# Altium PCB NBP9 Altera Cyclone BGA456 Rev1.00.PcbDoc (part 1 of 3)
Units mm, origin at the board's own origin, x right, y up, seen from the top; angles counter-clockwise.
Board outline 69 x 80.99 mm, 6 copper layers (Top Layer, MidLayer1, InternalPlane1, InternalPlane2, MidLayer2, Bottom Layer); 105 components, 269 nets, 899 pads, 453 vias.
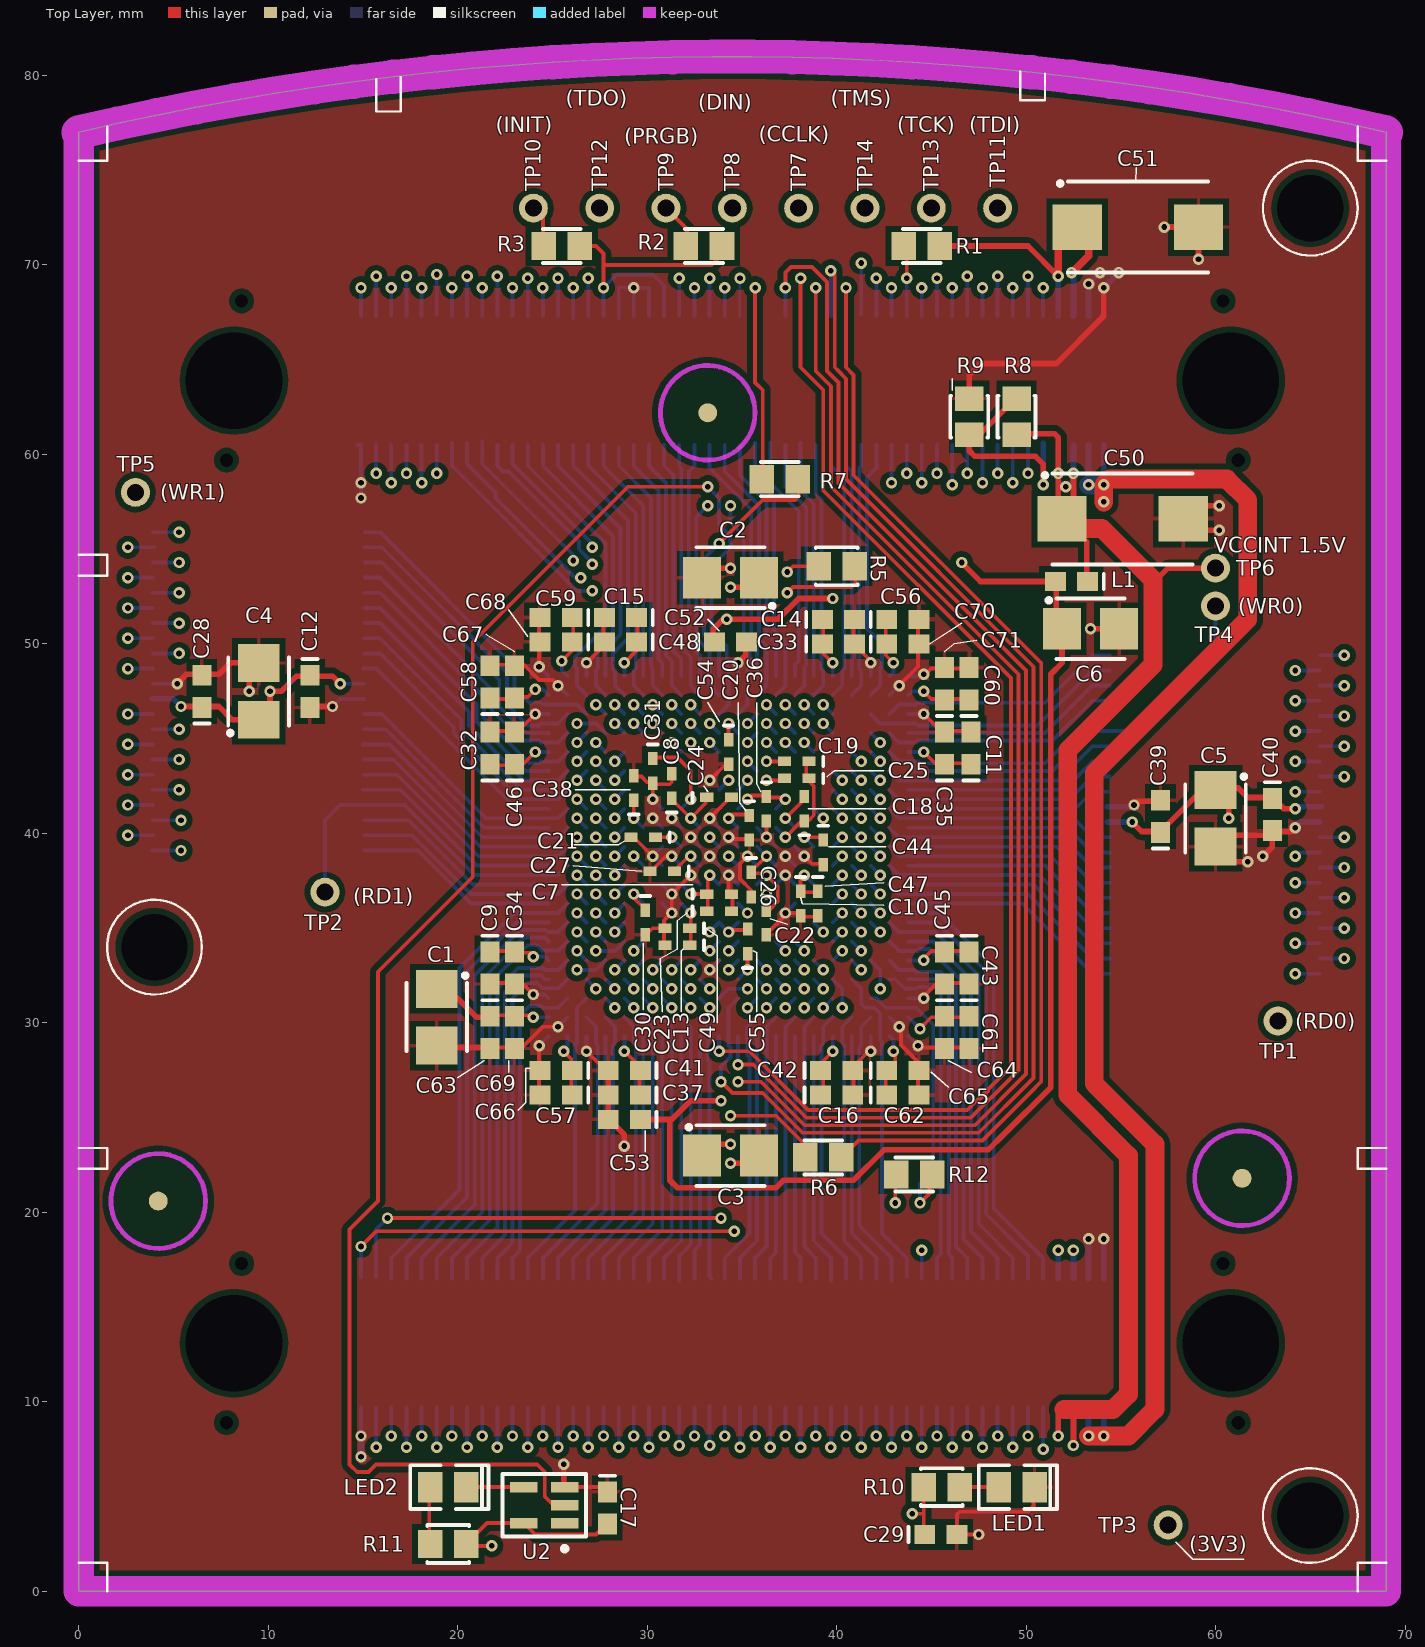
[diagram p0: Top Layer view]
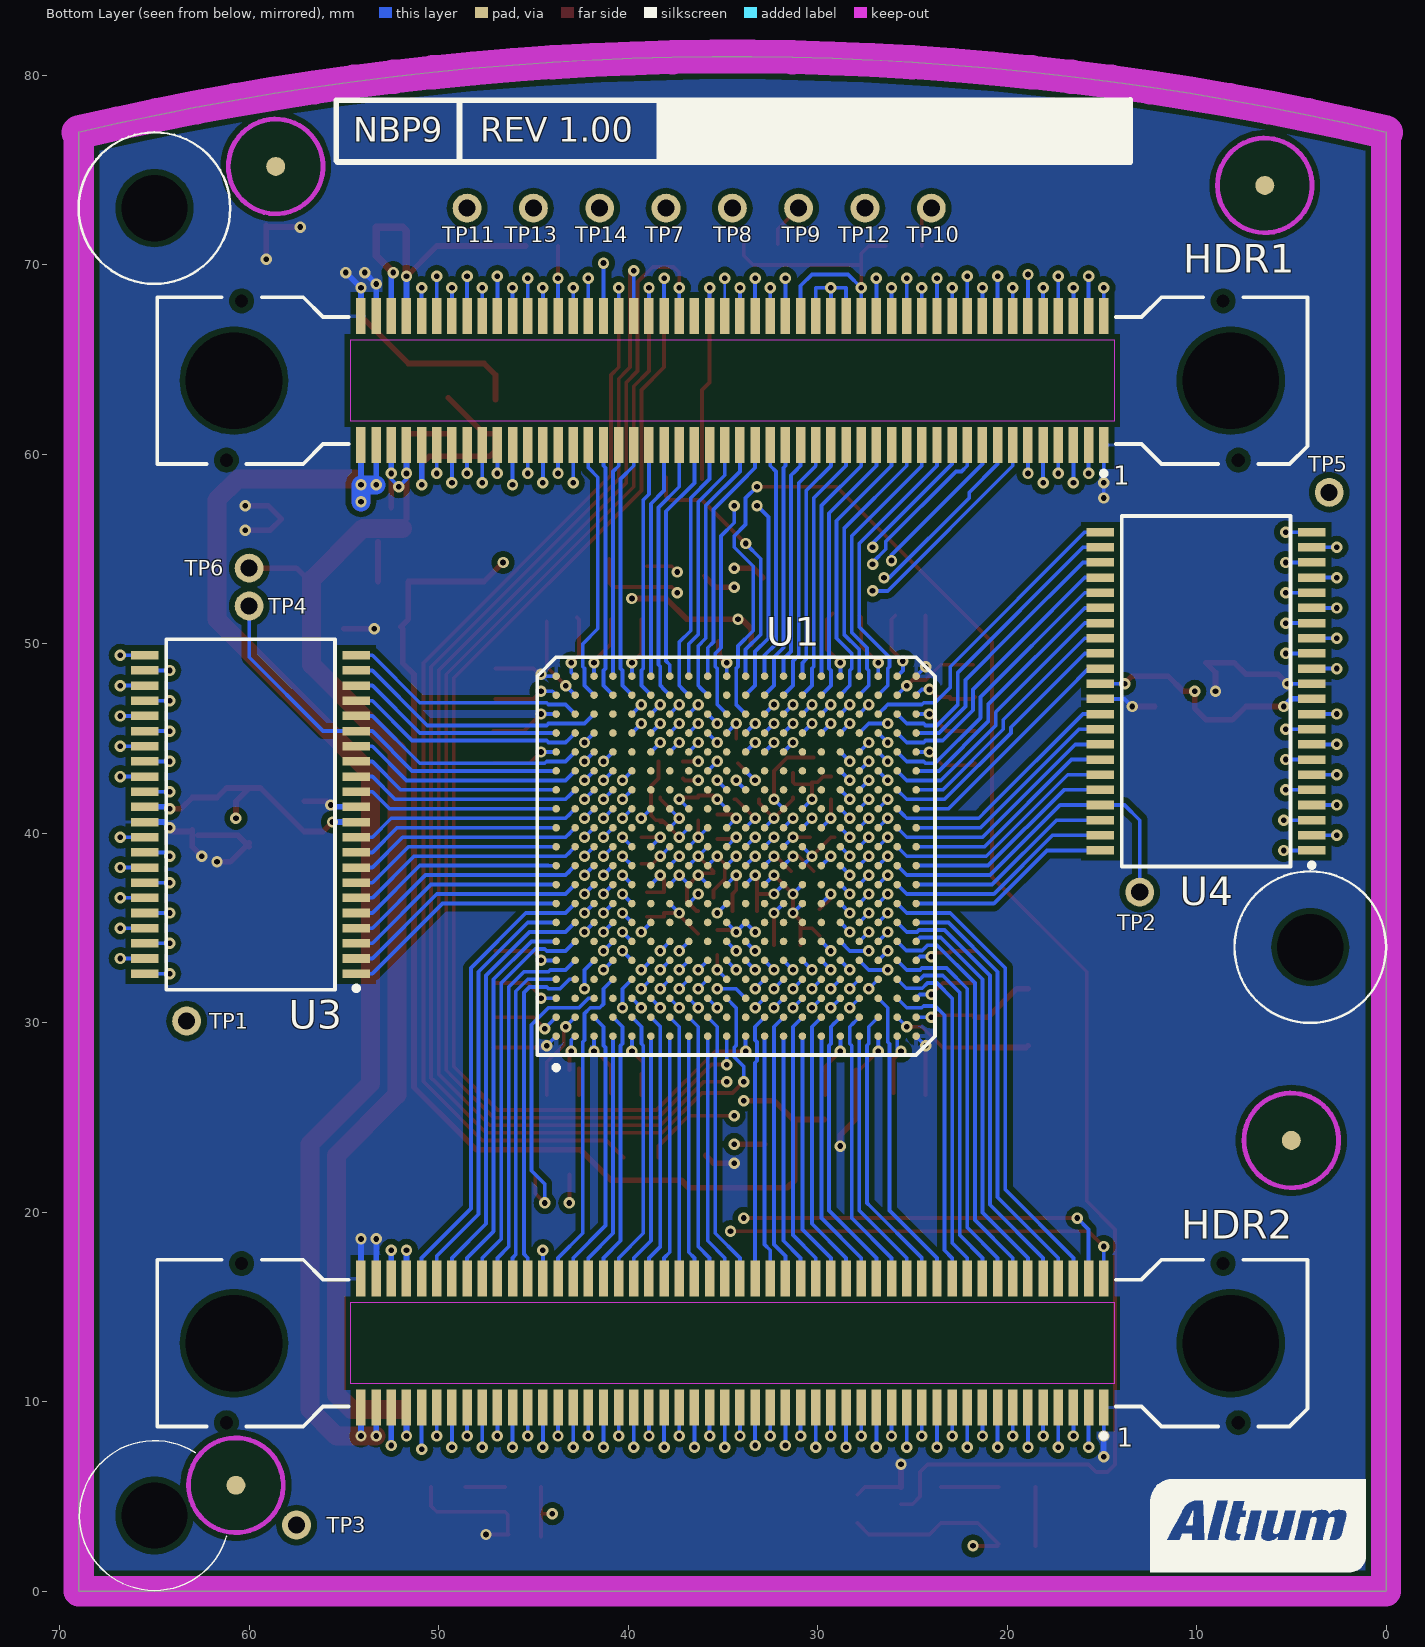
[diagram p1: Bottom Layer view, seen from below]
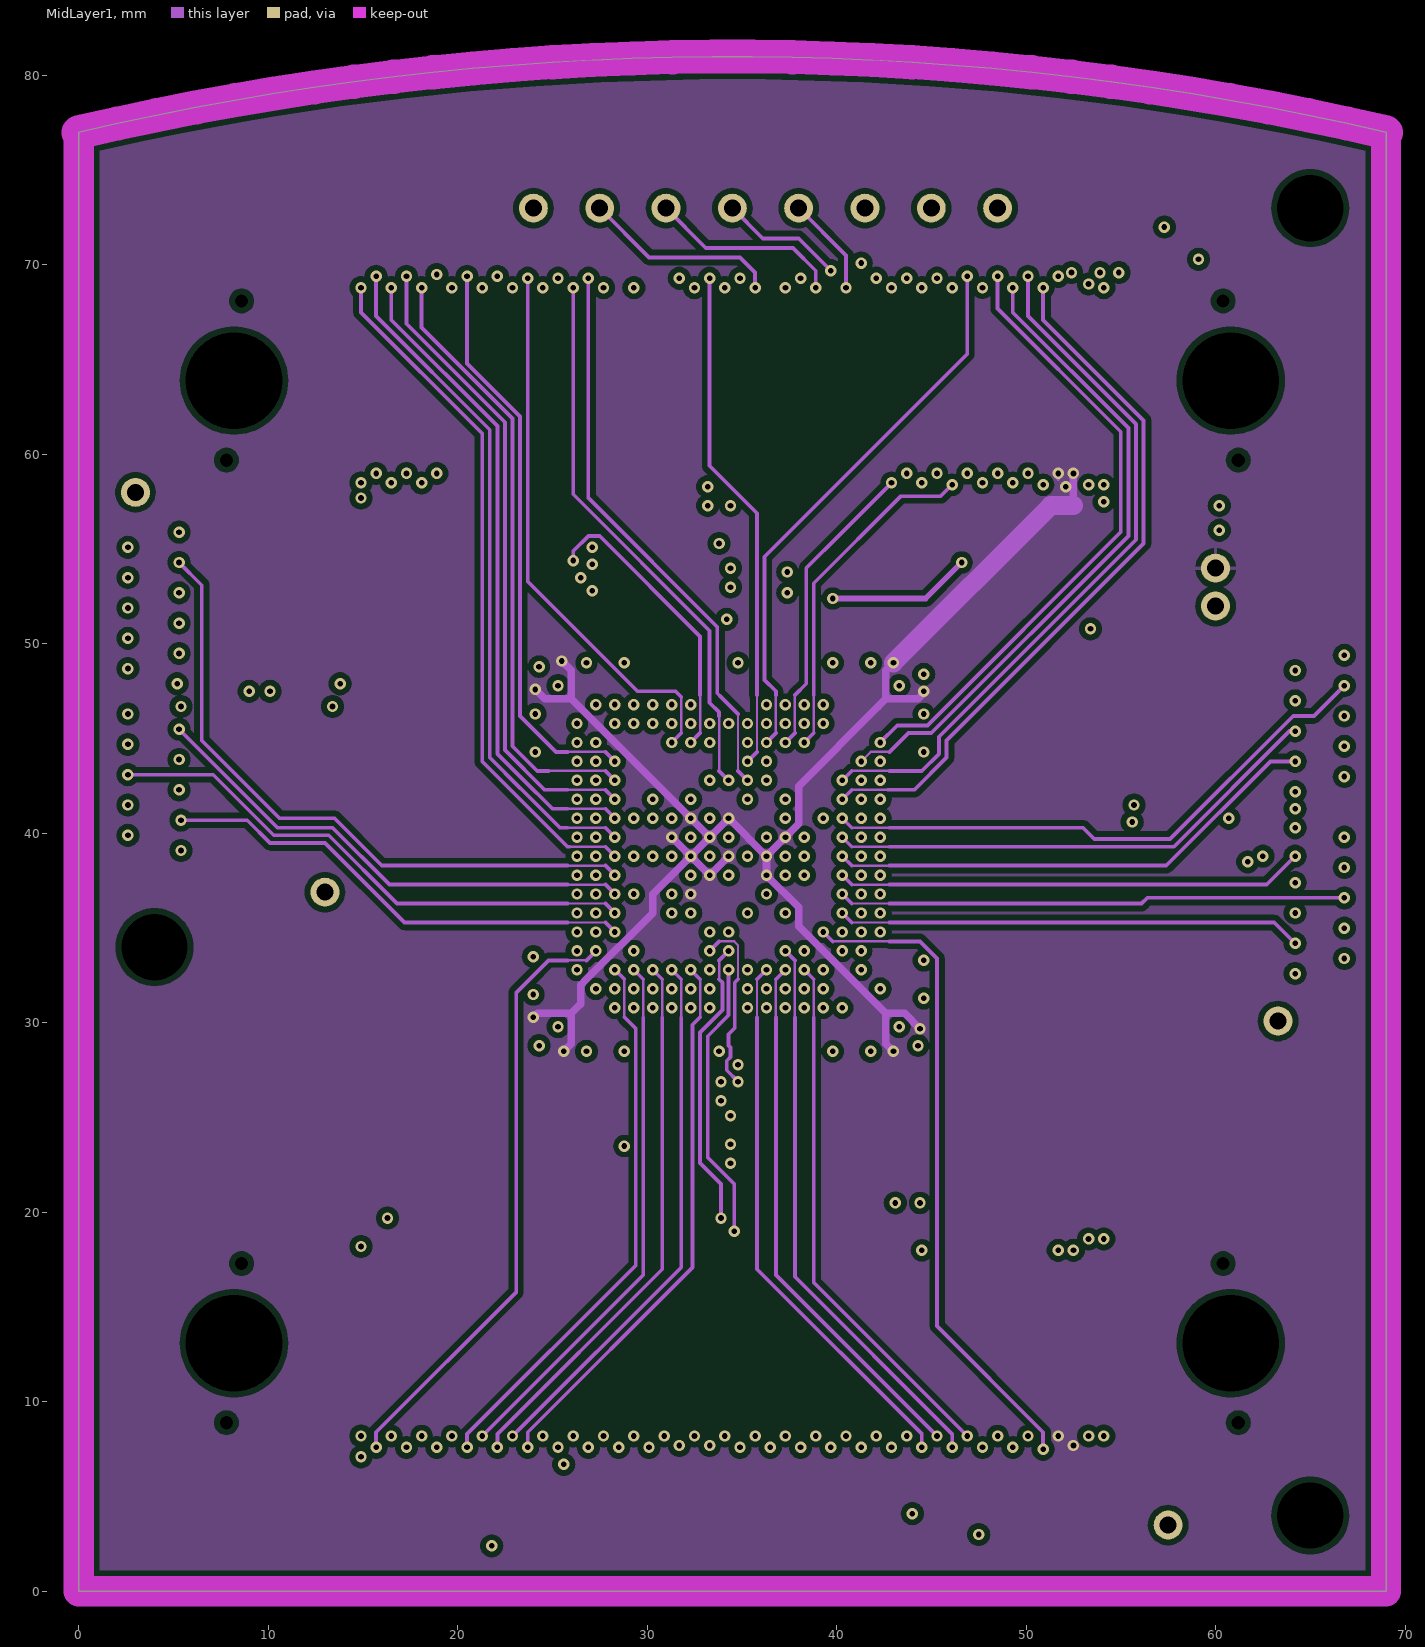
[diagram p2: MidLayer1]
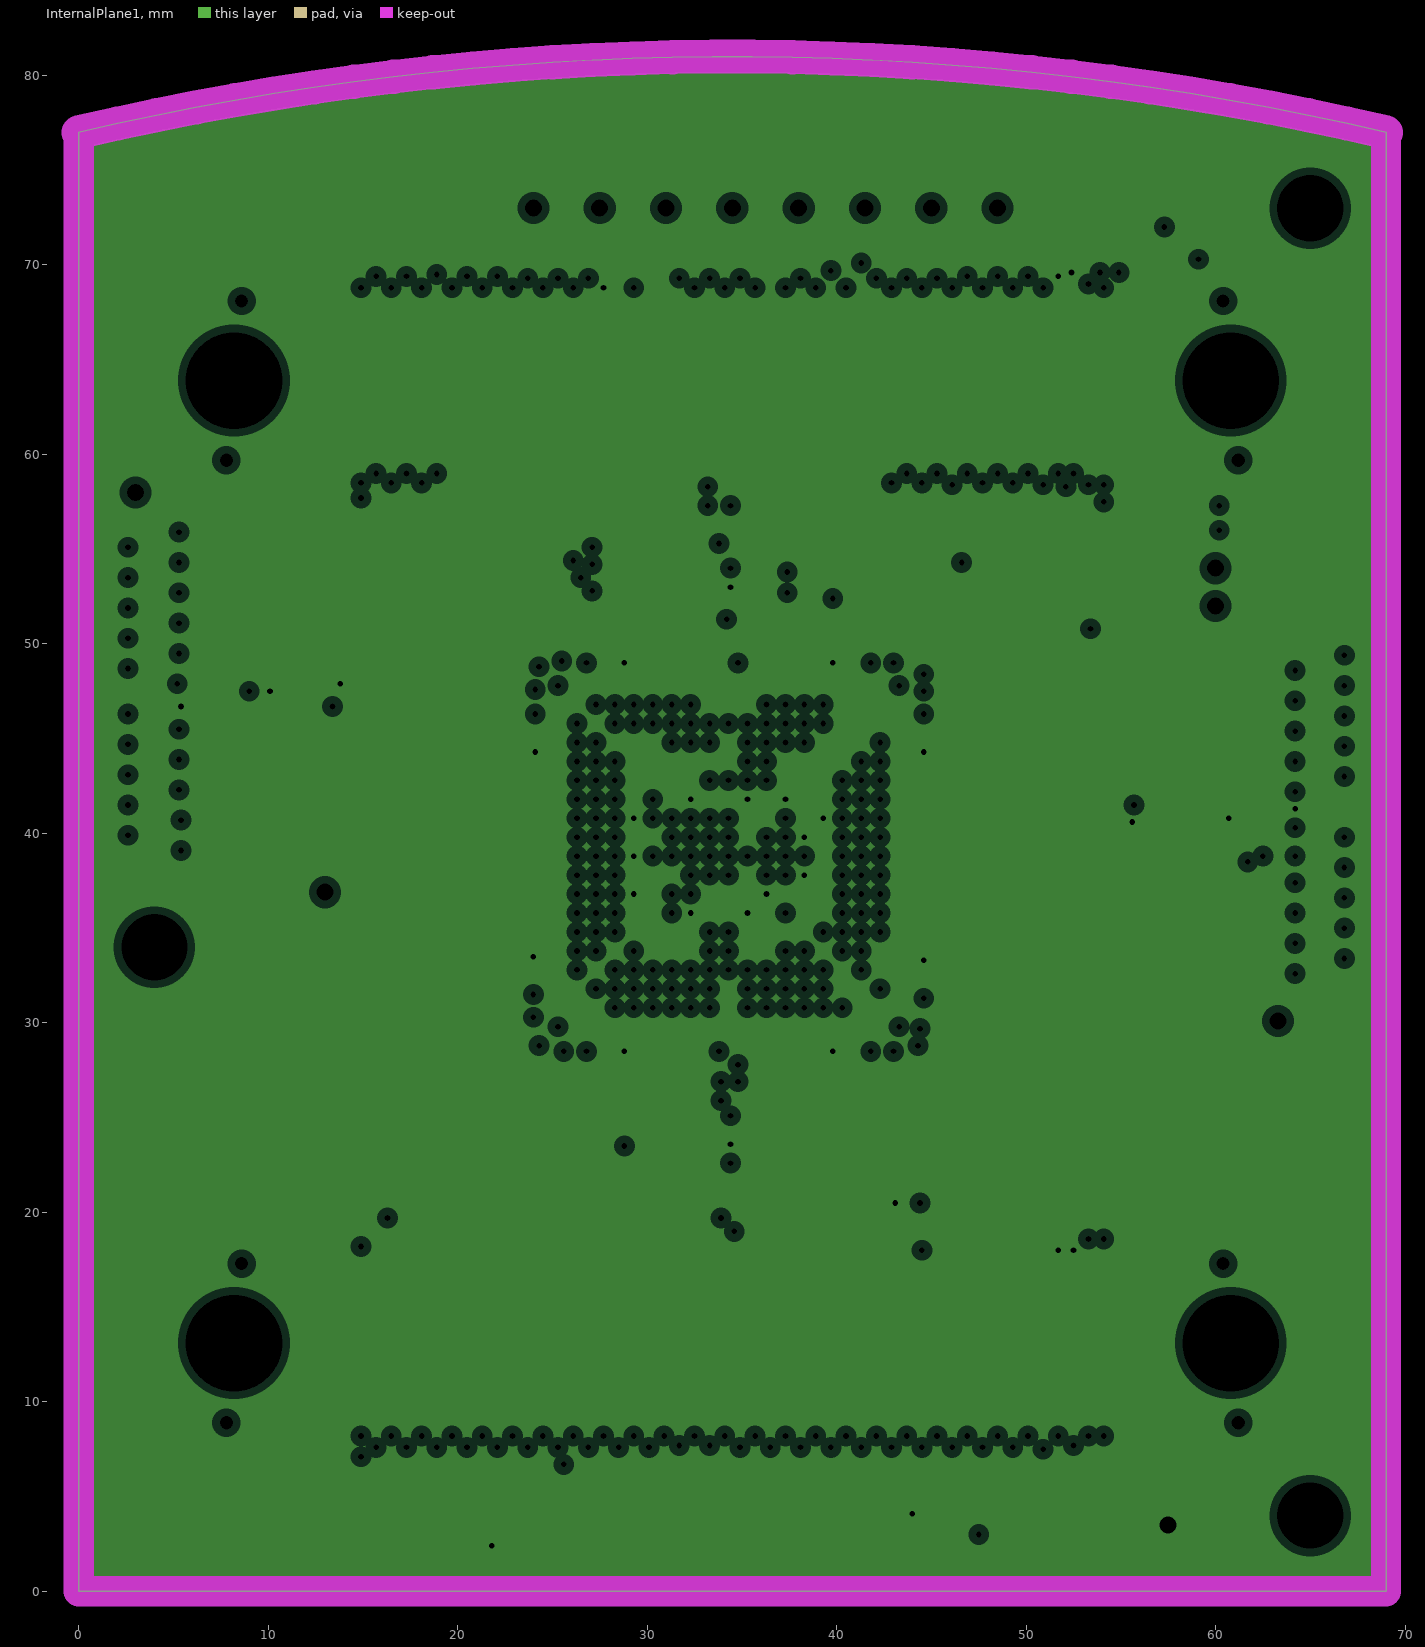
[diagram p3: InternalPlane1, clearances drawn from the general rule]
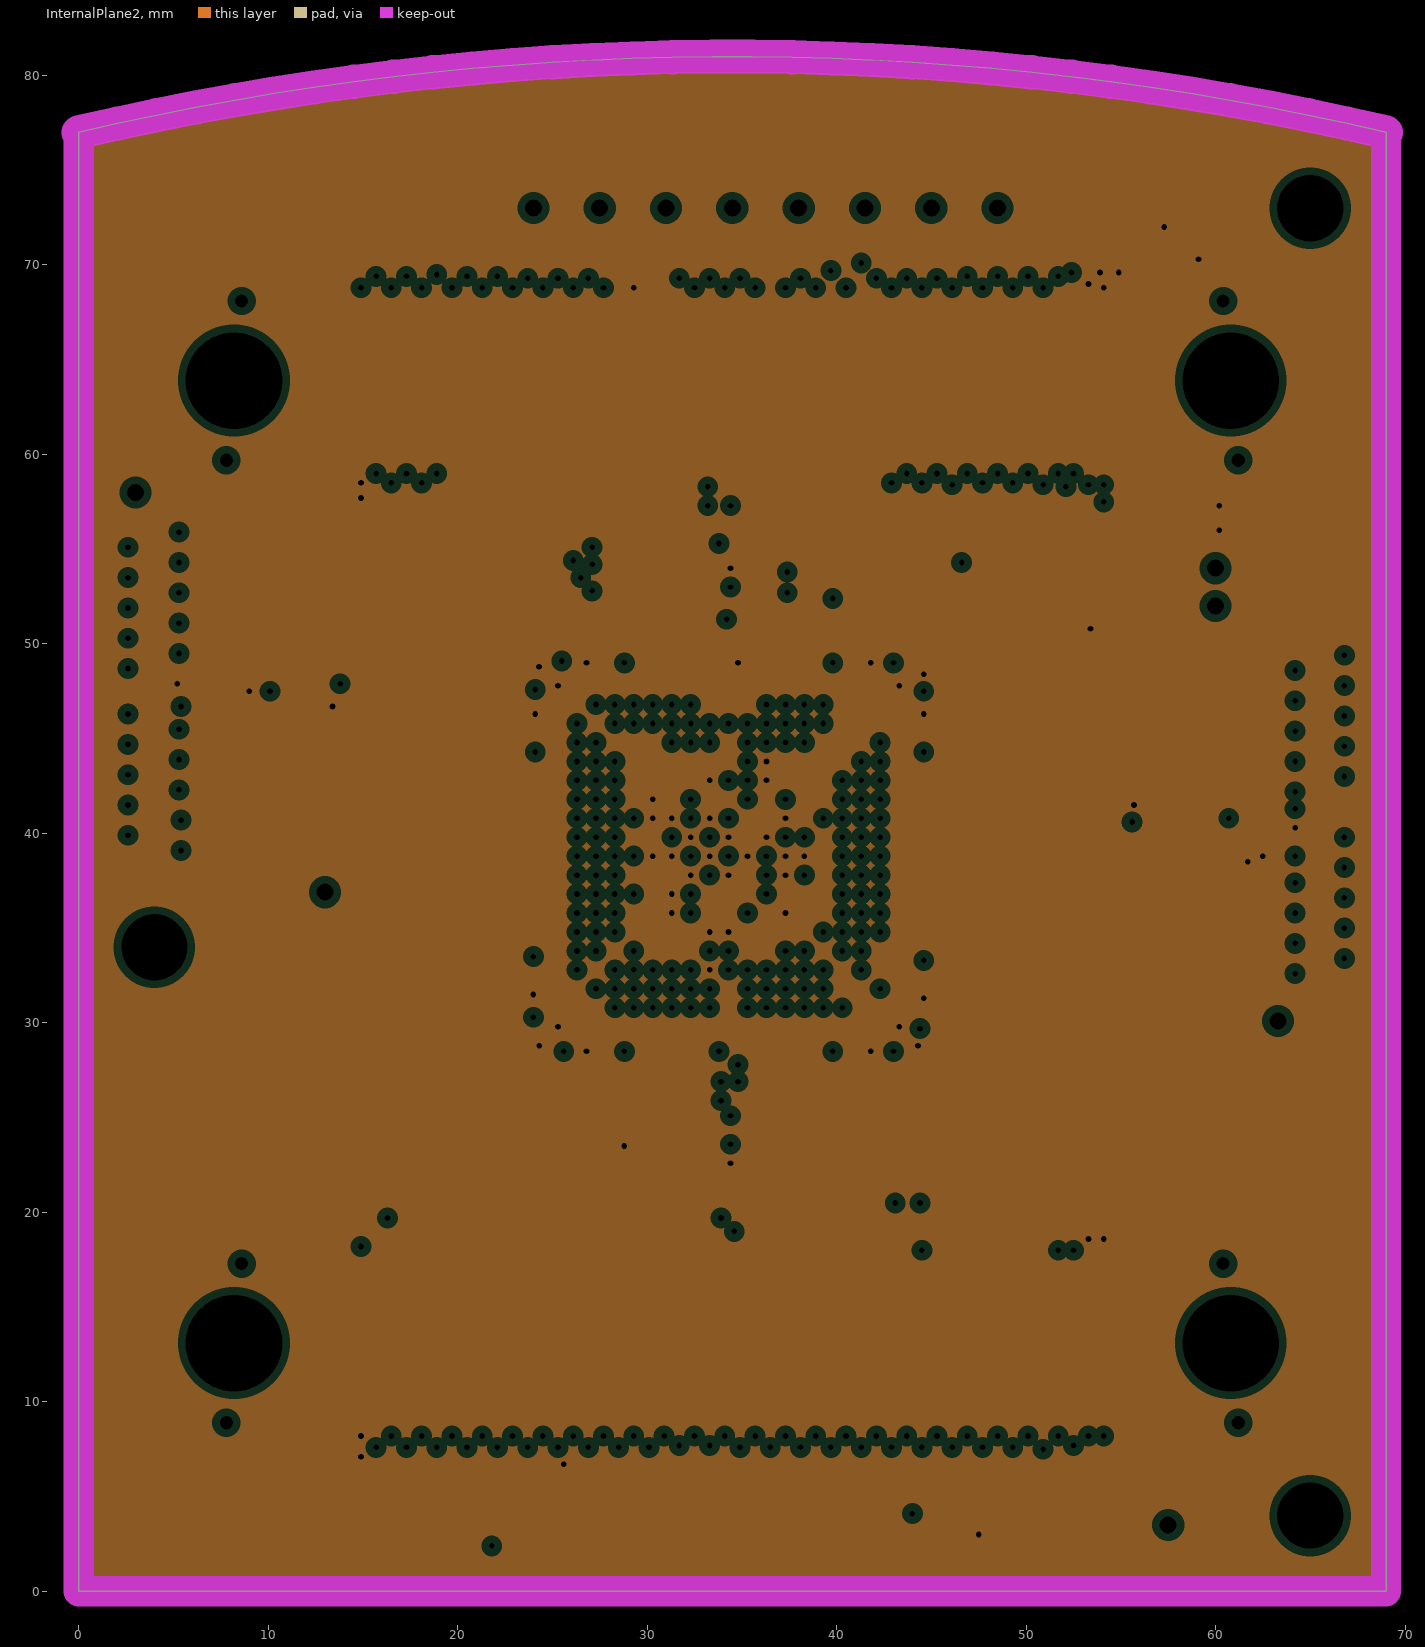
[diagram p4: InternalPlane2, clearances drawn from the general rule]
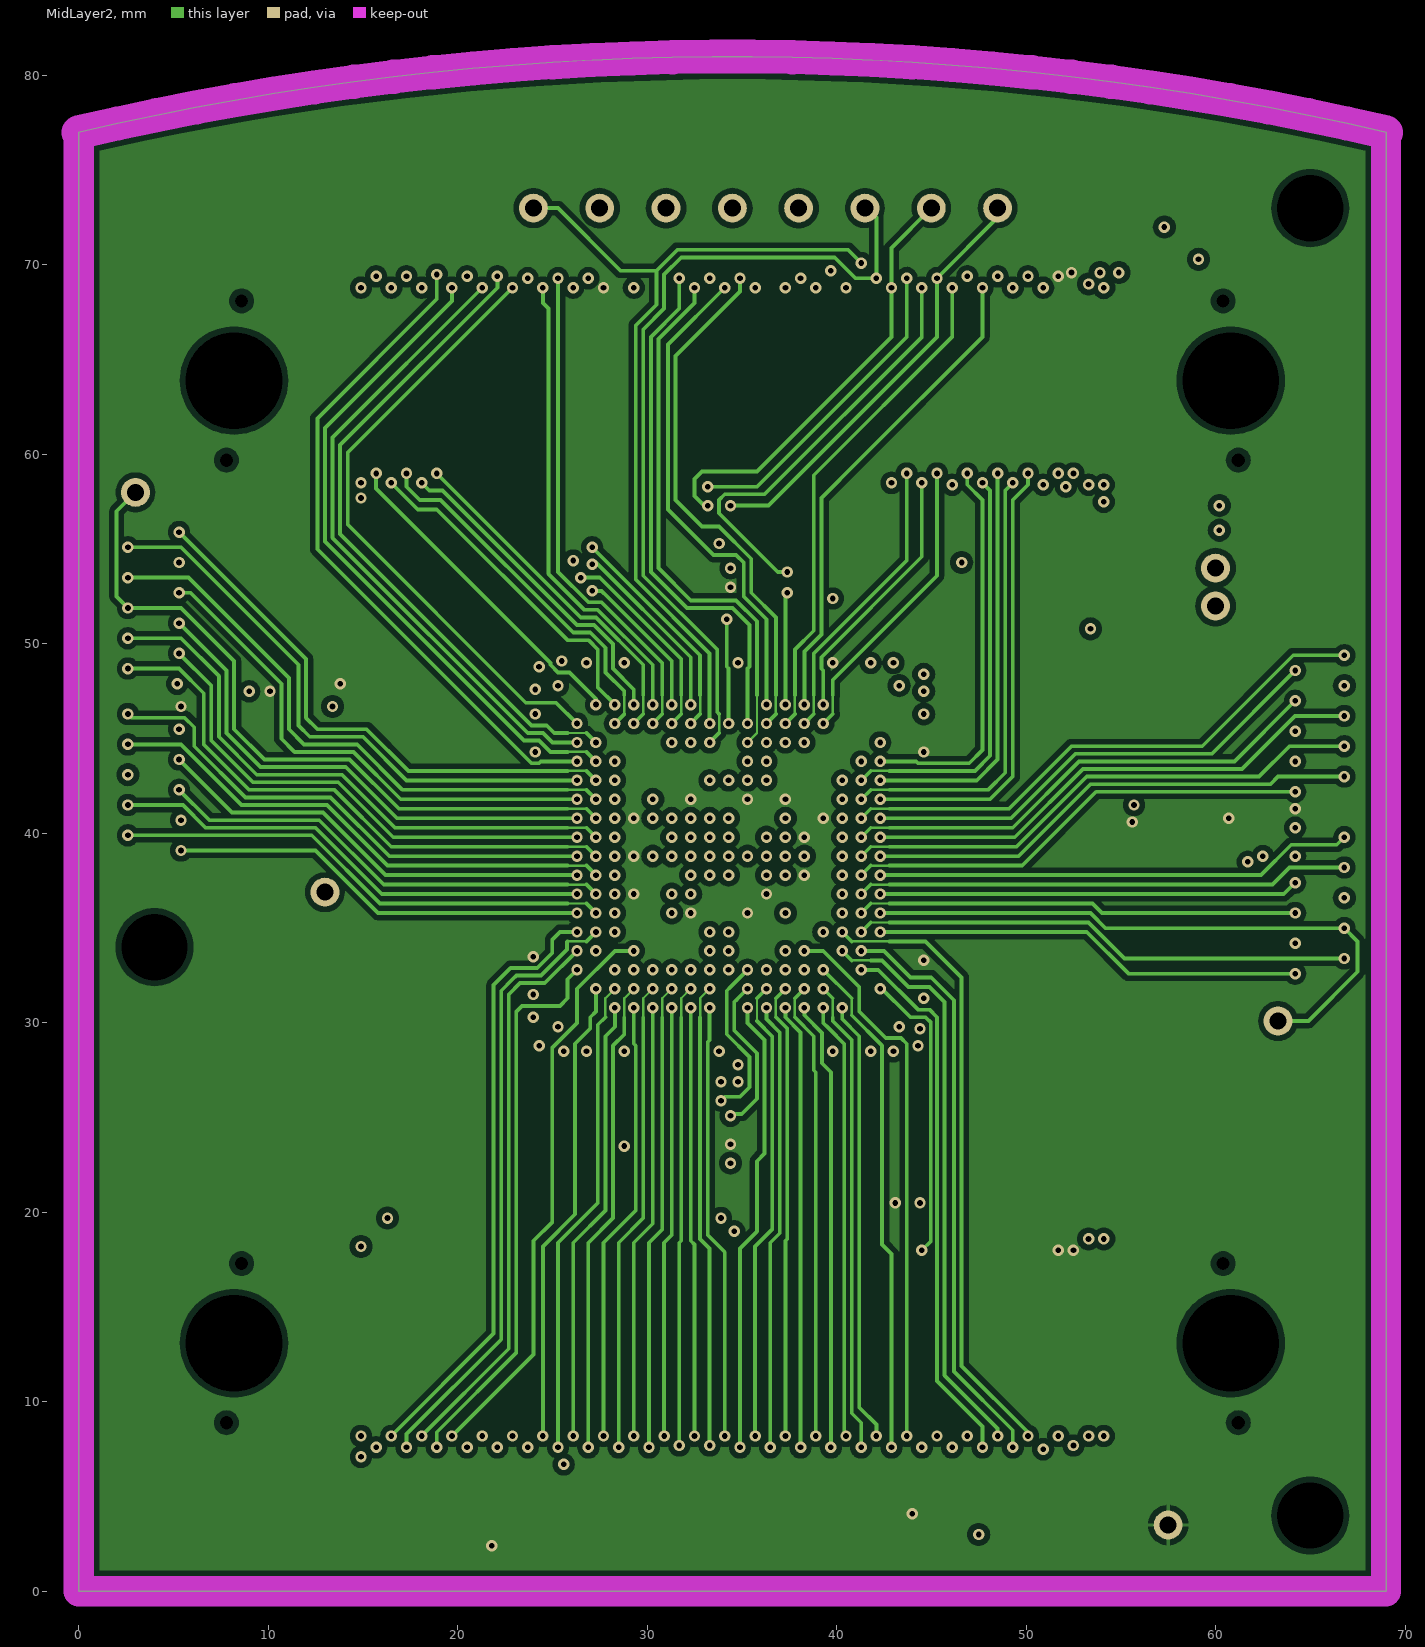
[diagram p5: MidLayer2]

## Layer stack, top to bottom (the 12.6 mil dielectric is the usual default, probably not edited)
Top Layer: signal copper 0.0356
Dielectric: core 0.32, FR-4, Dk 4.8
MidLayer1: signal copper 0.0356
Dielectric: prepreg 0.32, FR-4, Dk 4.8
InternalPlane1: plane copper 0.0356, net VCC
Dielectric: core 0.32, FR-4, Dk 4.8
InternalPlane2: plane copper 0.0356, net GND
Dielectric: prepreg 0.32, FR-4, Dk 4.8
MidLayer2: signal copper 0.0356
Dielectric: core 0.32, FR-4, Dk 4.8
Bottom Layer: signal copper 0.0356

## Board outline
0,0 0.001,77 cw(c34.5,-69.801) 69,77 69,0

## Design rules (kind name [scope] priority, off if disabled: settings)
Clearance Clearance_Polygons [InPolygon] p1: gap=0.3
Clearance "InnerLayer Track-Via Clearance" [OnMid And IsTrack vs IsVia] p2: gap=0.127
Clearance "Via-Via Clearance" [IsVia vs IsVia] p3: gap=0.3
Clearance "Pad-Pad Clearance Same Net" [IsPad vs IsPad] p4: gap=0.254
Clearance "Via-Pad Clearance" [IsVia vs IsPad] p5: gap=0.2
Clearance "General Clearance" [All] p6: gap=0.125
ComponentClearance [All] p1: gap=0.2 collisioncheckmode=3 verticalgap=0.254 showdistances=FALSE
FabricationTestPointUsage TestPointUsage [All] p1 off: valid=0 allowmultiple=FALSE
FabricationTestpoint Testpoint [All] p1 off: side=3 testpointundercomponent=TRUE minsize=1.016 maxsize=2.54 preferedsize=1.524 minholesize=0 maxholesize=1.016 preferedholesize=0.813 testpointgrid=0.025 allowsidetop=TRUE allowsidebottom=TRUE usegrid=TRUE gridtolerance=0
HoleSize [All] p1: absolutevalues=TRUE maxlimit=5.2 minlimit=0.25 maxpercent=80.000 minpercent=20.000
PlaneClearance [All] p1: clearance=0.4
PlaneConnect [All] p1: planeconnectstyle=Direct reliefexpansion=0.5 reliefentries=4 reliefconductorwidth=0.25 reliefairgap=0.25
PolygonConnect [All] p1: connectstyle=Relief reliefconductorwidth=0.2 reliefentries=4 polygonreliefangle="90 Angle"
RoutingVias [All] p1: holewidth=0.3 width=0.6 viastyle="Through Hole" minholewidth=0.3 minwidth=0.6 maxholewidth=0.5 maxwidth=0.9
SMDNeckDown [All] p1: percent=100.000
SilkscreenOverComponentPads [All] p1: minsilkscreentomaskgap=0.254
SolderMaskExpansion SolderMaskExpansion_Vias [IsVia] p1: expansion=-0.65
SolderMaskExpansion [All] p2: expansion=0.1
Width [All] p1: maxlimit=2.5 minlimit=0.127 preferedwidth=0.4 toplayer_minwidth=0.2 toplayer_prefwidth=0.2 midlayer2_prefwidth=0.2 bottomlayer_prefwidth=0.3 minimp=50.000000 maximp=50.000000 favimp=50.000000
21 further rules are at their usual default settings.

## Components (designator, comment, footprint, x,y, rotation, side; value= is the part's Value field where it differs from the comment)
C1 "10uF" MCCT-B 18.9,30.3 r270 top
C2 "10uF" MCCT-B 34.4,53.5 r180 top
C3 "10uF" MCCT-B 34.4,23 r0 top
C4 "10uF" MCCT-B 9.5,47.5 r90 top
C5 "10uF" MCCT-B 60,40.8 r270 top
C6 "10uF" MCCT-B 53.4,50.8 r0 top
C7 "220nF" CC1005-0402 33.8,36.8 r0 top
C8 "220nF" CC1005-0402 31.3,42.5 r90 top
C9 "220nF" CC1608-0603 21.7,32.9 r270 top
C10 "220nF" CC1005-0402 38.1,36.3 r270 top
C11 "220nF" CC1608-0603 47.1,44.5 r90 top
C12 "220nF" CC1608-0603 12.2,47.5 r270 top
C13 "220nF" CC1005-0402 31.6,34.1 r180 top
C14 "220nF" CC1608-0603 40.1,51.3 r0 top
C15 "220nF" CC1608-0603 28.6,51.4 r180 top
C16 "220nF" CC1608-0603 40,26.2 r0 top
C17 "220nF" CC1608-0603 27.9,4.4 r270 top
C18 "10nF" CC1005-0402 38.3,41.3 r90 top
C19 "10nF" CC1005-0402 37.9,43.8 r180 top
C20 "10nF" CC1005-0402 35.4,40.3 r270 top
C21 "10nF" CC1005-0402 29.8,39.8 r180 top
C22 "10nF" CC1005-0402 36.3,35.3 r270 top
C23 "10nF" CC1005-0402 33.8,35.9 r0 top
C24 "10nF" CC1005-0402 33.8,41.9 r0 top
C25 "10nF" CC1005-0402 37.9,42.9 r180 top
C26 "10nF" CC1005-0402 35.5,37.3 r270 top
C27 "10nF" CC1005-0402 30.8,38 r180 top
C28 "10nF" CC1608-0603 6.5,47.5 r90 top
C29 "10nF" CC1608-0603 45.5,3 r0 top
C30 "10nF" CC1005-0402 29.9,35.3 r270 top
C31 "10nF" CC1005-0402 30.3,43.3 r270 top
C32 "220nF" CC1608-0603 21.7,44.5 r90 top
C33 "10nF" CC1608-0603 40.1,50 r0 top
C34 "10nF" CC1608-0603 23,32.9 r270 top
C35 "10nF" CC1608-0603 45.7,44.5 r90 top
C36 "10nF" CC1005-0402 36.3,41.3 r270 top
C37 "220nF" CC1608-0603 28.8,26.2 r180 top
C38 "10nF" CC1005-0402 29.3,42.4 r90 top
C39 "10nF" CC1608-0603 57.1,40.9 r90 top
C40 "10nF" CC1608-0603 63,41 r270 top
C41 "10nF" CC1608-0603 28.8,27.5 r180 top
C42 "10nF" CC1608-0603 40,27.5 r0 top
C43 "220nF" CC1608-0603 47,32.9 r270 top
C44 "10nF" CC1005-0402 39.3,39 r270 top
C45 "10nF" CC1608-0603 45.7,32.9 r270 top
C46 "10nF" CC1608-0603 23,44.5 r90 top
C47 "10nF" CC1005-0402 39,36.3 r270 top
C48 "10nF" CC1608-0603 28.6,50.1 r180 top
C49 "10nF" CC1005-0402 31.6,35 r180 top
C50 "220uF/4V" MCCT-D 55.1,56.6 r0 top
C51 "220uF/4V" MCCT-D 55.9,72 r0 top
C52 "0.1uF" CC1608-0603 34.4,50.1 r0 top
C53 "0.1uF" CC1608-0603 28.8,24.9 r180 top
C54 "0.001uF" CC1005-0402 34.3,44.3 r270 top
C55 "0.001uF" CC1005-0402 35.3,34.3 r90 top
C56 "220nF" CC1608-0603 43.5,51.3 r0 top
C57 "220nF" CC1608-0603 25.2,26.2 r180 top
C58 "220nF" CC1608-0603 21.7,48 r90 top
C59 "220nF" CC1608-0603 25.2,51.4 r180 top
C60 "220nF" CC1608-0603 47,47.9 r90 top
C61 "220nF" CC1608-0603 47,29.5 r270 top
C62 "220nF" CC1608-0603 43.5,26.2 r0 top
C63 "220nF" CC1608-0603 21.7,29.5 r270 top
C64 "10nF" CC1608-0603 45.7,29.5 r270 top
C65 "10nF" CC1608-0603 43.5,27.5 r0 top
C66 "10nF" CC1608-0603 25.2,27.5 r180 top
C67 "10nF" CC1608-0603 23,48 r90 top
C68 "10nF" CC1608-0603 25.2,50.1 r180 top
C69 "10nF" CC1608-0603 23,29.5 r270 top
C70 "10nF" CC1608-0603 43.5,50 r0 top
C71 "10nF" CC1608-0603 45.7,47.9 r90 top
HDR1 "54075-1009-HD1" 54075 34.5,63.9 r0 bottom locked
HDR2 "54075-1009-HD2" 54075 34.5,13.1 r0 bottom locked
L1 "Ferrite Bead 50Mhz" CC1608-0603 52.4,53.3 r180 top
LED1 "HSMH-C170" "SMD _LED" 49.5,5.5 r180 top locked
LED2 "HSMG-C170" "SMD _LED" 19.5,5.5 r180 top locked
R1 "4k7" CC2012-0805 44.5,71 r180 top
R2 "4k7" CC2012-0805 33,71 r180 top
R3 "4k7" CC2012-0805 25.5,71 r180 top
R5 "100R" CR2012-0805 40,54.1 r0 top
R6 "33R" CC2012-0805 39.3,22.9 r0 top
R7 "100R" CC2012-0805 37,58.7 r0 top
R8 "DO NOT INSTALL" CR2012-0805 49.5,62 r90 top
R9 "47R/1%" CR2012-0805 47,62 r90 top
R10 "270R" CR2012-0805 45.55,5.5 r0 top
R11 "270R" CR2012-0805 19.5,2.5 r0 top
R12 "4K7" CC2012-0805 44.1,22 r180 top
TP1 "(RD0)" TestPin 63.3,30.1 r0 top
TP2 "(RD1)" TestPin 13,36.9 r90 top
TP3 "(3V3)" TestPin 57.5,3.5 r90 top
TP4 "(WR0)" TestPin 60,52 r90 top
TP5 "(WR1)" TestPin 3,58 r90 top
TP6 "VCCINT 1.5V" TestPin 60,54 r90 top
TP7 "(CCLK)" TestPin 38,73 r90 top
TP8 "(DIN)" TestPin 34.5,73 r90 top
TP9 "(PRGB)" TestPin 31,73 r90 top
TP10 "(INIT)" TestPin 24,73 r90 top
TP11 "(TDI)" TestPin 48.5,73 r90 top
TP12 "(TDO)" TestPin 27.5,73 r90 top
TP13 "(TCK)" TestPin 45,73 r90 top
TP14 "(TMS)" TestPin 41.5,73 r90 top
U1 "EP1C20F400C8" FBGA400 81,63.5 r90 bottom locked
U2 "SN74LVC1G04DBV" SO-G5/P.95 24.575,4.55 r90 top
U3 "SRAM 512Kx16 TSOP44" SO-G44/P.8 59.925,41 r90 bottom
U4 "SRAM 512Kx16 TSOP44" SO-G44/P.8 9.5,47.5 r90 bottom

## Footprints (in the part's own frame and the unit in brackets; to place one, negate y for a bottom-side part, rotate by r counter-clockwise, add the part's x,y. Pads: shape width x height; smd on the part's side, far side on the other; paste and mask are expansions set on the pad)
54075 [mm] "Connector; Docking Station, Receptacle; 100 Position; Vertical"
  rect 0.5x1.9 smd: 1(-19.6,3.4) 2(-19.6,-3.4) 3(-18.8,3.4) 4(-18.8,-3.4) 5(-18,3.4) 6(-18,-3.4) 7(-17.2,3.4) 8(-17.2,-3.4) 9(-16.4,3.4) 10(-16.4,-3.4) 11(-15.6,3.4) 12(-15.6,-3.4) 13(-14.8,3.4) 14(-14.8,-3.4) 15(-14,3.4) 16(-14,-3.4) 17(-13.2,3.4) 18(-13.2,-3.4) 19(-12.4,3.4) 20(-12.4,-3.4) 21(-11.6,3.4) 22(-11.6,-3.4) 23(-10.8,3.4) 24(-10.8,-3.4) 25(-10,3.4) 26(-10,-3.4) 27(-9.2,3.4) 28(-9.2,-3.4) 29(-8.4,3.4) 30(-8.4,-3.4) 31(-7.6,3.4) 32(-7.6,-3.4) 33(-6.8,3.4) 34(-6.8,-3.4) 35(-6,3.4) 36(-6,-3.4) 37(-5.2,3.4) 38(-5.2,-3.4) 39(-4.4,3.4) 40(-4.4,-3.4) 41(-3.6,3.4) 42(-3.6,-3.4) 43(-2.8,3.4) 44(-2.8,-3.4) 45(-2,3.4) 46(-2,-3.4) 47(-1.2,3.4) 48(-1.2,-3.4) 49(-0.4,3.4) 50(-0.4,-3.4) 51(0.4,3.4) 52(0.4,-3.4) 53(1.2,3.4) 54(1.2,-3.4) 55(2,3.4) 56(2,-3.4) 57(2.8,3.4) 58(2.8,-3.4) 59(3.6,3.4) 60(3.6,-3.4) 61(4.4,3.4) 62(4.4,-3.4) 63(5.2,3.4) 64(5.2,-3.4) 65(6,3.4) 66(6,-3.4) 67(6.8,3.4) 68(6.8,-3.4) 69(7.6,3.4) 70(7.6,-3.4) 71(8.4,3.4) 72(8.4,-3.4) 73(9.2,3.4) 74(9.2,-3.4) 75(10,3.4) 76(10,-3.4) 77(10.8,3.4) 78(10.8,-3.4) 79(11.6,3.4) 80(11.6,-3.4) 81(12.4,3.4) 82(12.4,-3.4) 83(13.2,3.4) 84(13.2,-3.4) 85(14,3.4) 86(14,-3.4) 87(14.8,3.4) 88(14.8,-3.4) 89(15.6,3.4) 90(15.6,-3.4) 91(16.4,3.4) 92(16.4,-3.4) 93(17.2,3.4) 94(17.2,-3.4) 95(18,3.4) 96(18,-3.4) 97(18.8,3.4) 98(18.8,-3.4) 99(19.6,3.4) 100(19.6,-3.4)
  round 0.5 hole 0.7 unplated: MH1(-26.7,4.2) MH2(-25.9,-4.2) MH3(26.7,4.2) MH4(25.9,-4.2)
  round 4.8 hole 5.1 unplated: MH5(-26.3,0) MH6(26.3,0)
  Top Layer keep-out region: -20.15,2.15 20.15,2.15 20.15,-2.15 -20.15,-2.15
  silkscreen extent -30.35,-4.4 30.35,5.02
CC1005-0402 [mm] "Chip Capacitor; Body 1.0 x 0.5 mm (LxW typ)"
  rect 0.7x0.5 smd: 1(-0.65,0) 2(0.65,0)
  silkscreen extent -1.4,-0.25 -1.4,0.25
CC1608-0603 [mm] "Chip Capacitor; Body 1.6 x 0.8 mm (LxW typ)"
  rect 1.1x1 smd: 1(-0.85,0) 2(0.85,0)
  silkscreen extent -1.7,-0.4 -1.7,0.4
CC2012-0805 [mm]
  rect 1.3x1.5 smd: 1(-0.95,0) 2(0.95,0)
  silkscreen extent -1,-0.9 1,0.9
CR2012-0805 [mm]
  rect 1.3x1.5 smd: 1(-0.95,0) 2(0.95,0)
  silkscreen extent -1.1,-1 1.1,1
FBGA400 [mm] "400-Pin Non-Thermally Enhanced FineLine Ball-Grid Array (FBGA)"
  round 0.4 smd: A1(-34.2,-37.2) A2(-33.2,-37.2) A3(-32.2,-37.2) A4(-31.2,-37.2) A5(-30.2,-37.2) A6(-29.2,-37.2) A7(-28.2,-37.2) A8(-27.2,-37.2) A9(-26.2,-37.2) A10(-25.2,-37.2) A11(-24.2,-37.2) A12(-23.2,-37.2) A13(-22.2,-37.2) A14(-21.2,-37.2) A15(-20.2,-37.2) A16(-19.2,-37.2) A17(-18.2,-37.2) A18(-17.2,-37.2) A19(-16.2,-37.2) A20(-15.2,-37.2) B1(-34.2,-38.2) B2(-33.2,-38.2) B3(-32.2,-38.2) B4(-31.2,-38.2) B5(-30.2,-38.2) B6(-29.2,-38.2) B7(-28.2,-38.2) B8(-27.2,-38.2) B9(-26.2,-38.2) B10(-25.2,-38.2) B11(-24.2,-38.2) B12(-23.2,-38.2) B13(-22.2,-38.2) B14(-21.2,-38.2) B15(-20.2,-38.2) B16(-19.2,-38.2) B17(-18.2,-38.2) B18(-17.2,-38.2) B19(-16.2,-38.2) B20(-15.2,-38.2) C1(-34.2,-39.2) C2(-33.2,-39.2) C3(-32.2,-39.2) C4(-31.2,-39.2) C5(-30.2,-39.2) C6(-29.2,-39.2) C7(-28.2,-39.2) C8(-27.2,-39.2) C9(-26.2,-39.2) C10(-25.2,-39.2) C11(-24.2,-39.2) C12(-23.2,-39.2) C13(-22.2,-39.2) C14(-21.2,-39.2) C15(-20.2,-39.2) C16(-19.2,-39.2) C17(-18.2,-39.2) C18(-17.2,-39.2) C19(-16.2,-39.2) C20(-15.2,-39.2) D1(-34.2,-40.2) D2(-33.2,-40.2) D3(-32.2,-40.2) D4(-31.2,-40.2) D5(-30.2,-40.2) D6(-29.2,-40.2) D7(-28.2,-40.2) D8(-27.2,-40.2) D9(-26.2,-40.2) D10(-25.2,-40.2) D11(-24.2,-40.2) D12(-23.2,-40.2) D13(-22.2,-40.2) D14(-21.2,-40.2) D15(-20.2,-40.2) D16(-19.2,-40.2) D17(-18.2,-40.2) D18(-17.2,-40.2) D19(-16.2,-40.2) D20(-15.2,-40.2) E1(-34.2,-41.2) E2(-33.2,-41.2) E3(-32.2,-41.2) E4(-31.2,-41.2) E5(-30.2,-41.2) E6(-29.2,-41.2) E7(-28.2,-41.2) E8(-27.2,-41.2) E9(-26.2,-41.2) E10(-25.2,-41.2) E11(-24.2,-41.2) E12(-23.2,-41.2) E13(-22.2,-41.2) E14(-21.2,-41.2) E15(-20.2,-41.2) E16(-19.2,-41.2) E17(-18.2,-41.2) E18(-17.2,-41.2) E19(-16.2,-41.2) E20(-15.2,-41.2) F1(-34.2,-42.2) F2(-33.2,-42.2) F3(-32.2,-42.2) F4(-31.2,-42.2) F5(-30.2,-42.2) F6(-29.2,-42.2) F7(-28.2,-42.2) F8(-27.2,-42.2) F9(-26.2,-42.2) F10(-25.2,-42.2) F11(-24.2,-42.2) F12(-23.2,-42.2) F13(-22.2,-42.2) F14(-21.2,-42.2) F15(-20.2,-42.2) F16(-19.2,-42.2) F17(-18.2,-42.2) F18(-17.2,-42.2) F19(-16.2,-42.2) F20(-15.2,-42.2) G1(-34.2,-43.2) G2(-33.2,-43.2) G3(-32.2,-43.2) G4(-31.2,-43.2) G5(-30.2,-43.2) G6(-29.2,-43.2) G7(-28.2,-43.2) G8(-27.2,-43.2) G9(-26.2,-43.2) G10(-25.2,-43.2) G11(-24.2,-43.2) G12(-23.2,-43.2) G13(-22.2,-43.2) G14(-21.2,-43.2) G15(-20.2,-43.2) G16(-19.2,-43.2) G17(-18.2,-43.2) G18(-17.2,-43.2) G19(-16.2,-43.2) G20(-15.2,-43.2) H1(-34.2,-44.2) H2(-33.2,-44.2) H3(-32.2,-44.2) H4(-31.2,-44.2) H5(-30.2,-44.2) H6(-29.2,-44.2) H7(-28.2,-44.2) H8(-27.2,-44.2) H9(-26.2,-44.2) H10(-25.2,-44.2) H11(-24.2,-44.2) H12(-23.2,-44.2) H13(-22.2,-44.2) H14(-21.2,-44.2) H15(-20.2,-44.2) H16(-19.2,-44.2) H17(-18.2,-44.2) H18(-17.2,-44.2) H19(-16.2,-44.2) H20(-15.2,-44.2) J1(-34.2,-45.2) J2(-33.2,-45.2) J3(-32.2,-45.2) J4(-31.2,-45.2) J5(-30.2,-45.2) J6(-29.2,-45.2) J7(-28.2,-45.2) J8(-27.2,-45.2) J9(-26.2,-45.2) J10(-25.2,-45.2) J11(-24.2,-45.2) J12(-23.2,-45.2) J13(-22.2,-45.2) J14(-21.2,-45.2) J15(-20.2,-45.2) J16(-19.2,-45.2) J17(-18.2,-45.2) J18(-17.2,-45.2) J19(-16.2,-45.2) K1(-34.2,-46.2) K2(-33.2,-46.2) K3(-32.2,-46.2) K4(-31.2,-46.2) K5(-30.2,-46.2) K6(-29.2,-46.2) K7(-28.2,-46.2) K8(-27.2,-46.2) K9(-26.2,-46.2) K10(-25.2,-46.2) K11(-24.2,-46.2) K12(-23.2,-46.2) K13(-22.2,-46.2) K14(-21.2,-46.2) K15(-20.2,-46.2) K16(-19.2,-46.2) K17(-18.2,-46.2) K18(-17.2,-46.2) K19(-16.2,-46.2) L1(-34.2,-47.2) L2(-33.2,-47.2) L3(-32.2,-47.2) L4(-31.2,-47.2) L5(-30.2,-47.2) L6(-29.2,-47.2) L7(-28.2,-47.2) L8(-27.2,-47.2) L9(-26.2,-47.2) L10(-25.2,-47.2) L11(-24.2,-47.2) L12(-23.2,-47.2) L13(-22.2,-47.2) L14(-21.2,-47.2) L15(-20.2,-47.2) L16(-19.2,-47.2) L17(-18.2,-47.2) L18(-17.2,-47.2) L19(-16.2,-47.2) L20(-15.2,-47.2) M1(-34.2,-48.2) M2(-33.2,-48.2) M3(-32.2,-48.2) M4(-31.2,-48.2) M5(-30.2,-48.2) M6(-29.2,-48.2) M7(-28.2,-48.2) M8(-27.2,-48.2) M9(-26.2,-48.2) M10(-25.2,-48.2) M11(-24.2,-48.2) M12(-23.2,-48.2) M13(-22.2,-48.2) M14(-21.2,-48.2) M15(-20.2,-48.2) M16(-19.2,-48.2) M17(-18.2,-48.2) M18(-17.2,-48.2) M19(-16.2,-48.2) M20(-15.2,-48.2) N1(-34.2,-49.2) N2(-33.2,-49.2) N3(-32.2,-49.2) N4(-31.2,-49.2) N5(-30.2,-49.2) N6(-29.2,-49.2) N7(-28.2,-49.2) N8(-27.2,-49.2) N9(-26.2,-49.2) N10(-25.2,-49.2) N11(-24.2,-49.2) N12(-23.2,-49.2) N13(-22.2,-49.2) N14(-21.2,-49.2) N15(-20.2,-49.2) N16(-19.2,-49.2) N17(-18.2,-49.2) N18(-17.2,-49.2) N19(-16.2,-49.2) N20(-15.2,-49.2) P1(-34.2,-50.2) P2(-33.2,-50.2) P3(-32.2,-50.2) P4(-31.2,-50.2) P5(-30.2,-50.2) P6(-29.2,-50.2) P7(-28.2,-50.2) P8(-27.2,-50.2) P9(-26.2,-50.2) P10(-25.2,-50.2) P11(-24.2,-50.2) P12(-23.2,-50.2) P13(-22.2,-50.2) P14(-21.2,-50.2) P15(-20.2,-50.2) P16(-19.2,-50.2) P17(-18.2,-50.2) P18(-17.2,-50.2) P19(-16.2,-50.2) P20(-15.2,-50.2) R1(-34.2,-51.2) R2(-33.2,-51.2) R3(-32.2,-51.2) R4(-31.2,-51.2) R5(-30.2,-51.2) R6(-29.2,-51.2) R7(-28.2,-51.2) R8(-27.2,-51.2) R9(-26.2,-51.2) R10(-25.2,-51.2) R11(-24.2,-51.2) R12(-23.2,-51.2) R13(-22.2,-51.2) R14(-21.2,-51.2) R15(-20.2,-51.2) R16(-19.2,-51.2) R17(-18.2,-51.2) R18(-17.2,-51.2) R19(-16.2,-51.2) R20(-15.2,-51.2) T1(-34.2,-52.2) T2(-33.2,-52.2) T3(-32.2,-52.2) T4(-31.2,-52.2) T5(-30.2,-52.2) T6(-29.2,-52.2) T7(-28.2,-52.2) T8(-27.2,-52.2) T9(-26.2,-52.2) T10(-25.2,-52.2) T11(-24.2,-52.2) T12(-23.2,-52.2) T13(-22.2,-52.2) T14(-21.2,-52.2) T15(-20.2,-52.2) T16(-19.2,-52.2) T17(-18.2,-52.2) T18(-17.2,-52.2) T19(-16.2,-52.2) T20(-15.2,-52.2) U1(-34.2,-53.2) U2(-33.2,-53.2) U3(-32.2,-53.2) U4(-31.2,-53.2) U5(-30.2,-53.2) U6(-29.2,-53.2) U7(-28.2,-53.2) U8(-27.2,-53.2) U9(-26.2,-53.2) U10(-25.2,-53.2) U11(-24.2,-53.2) U12(-23.2,-53.2) U13(-22.2,-53.2) U14(-21.2,-53.2) U15(-20.2,-53.2) U16(-19.2,-53.2) U17(-18.2,-53.2) U18(-17.2,-53.2) U19(-16.2,-53.2) U20(-15.2,-53.2) V1(-34.2,-54.2) V2(-33.2,-54.2) V3(-32.2,-54.2) V4(-31.2,-54.2) V5(-30.2,-54.2) V6(-29.2,-54.2) V7(-28.2,-54.2) V8(-27.2,-54.2) V9(-26.2,-54.2) V10(-25.2,-54.2) V11(-24.2,-54.2) V12(-23.2,-54.2) V13(-22.2,-54.2) V14(-21.2,-54.2) V15(-20.2,-54.2) V16(-19.2,-54.2) V17(-18.2,-54.2) V18(-17.2,-54.2) V19(-16.2,-54.2) V20(-15.2,-54.2) W1(-34.2,-55.2) W2(-33.2,-55.2) W3(-32.2,-55.2) W4(-31.2,-55.2) W5(-30.2,-55.2) W6(-29.2,-55.2) W7(-28.2,-55.2) W8(-27.2,-55.2) W9(-26.2,-55.2) W10(-25.2,-55.2) W11(-24.2,-55.2) W12(-23.2,-55.2) W13(-22.2,-55.2) W14(-21.2,-55.2) W15(-20.2,-55.2) W16(-19.2,-55.2) W17(-18.2,-55.2) W18(-17.2,-55.2) W19(-16.2,-55.2) W20(-15.2,-55.2) Y1(-34.2,-56.2) Y2(-33.2,-56.2) Y3(-32.2,-56.2) Y4(-31.2,-56.2) Y5(-30.2,-56.2) Y6(-29.2,-56.2) Y7(-28.2,-56.2) Y8(-27.2,-56.2) Y9(-26.2,-56.2) Y10(-25.2,-56.2) Y11(-24.2,-56.2) Y12(-23.2,-56.2) Y13(-22.2,-56.2) Y14(-21.2,-56.2) Y15(-20.2,-56.2) Y16(-19.2,-56.2) Y17(-18.2,-56.2) Y18(-17.2,-56.2) Y19(-16.2,-56.2) Y20(-15.2,-56.2)
  round 0.399 smd: J20(-15.2,-45.2) K20(-15.2,-46.2)
  silkscreen extent -35.98,-57.2 -14.2,-36.2
MCCT-B [mm]
  rect 2x2.2 smd: 1(-1.5,0) 2(1.5,0)
  silkscreen extent -2.3,-1.6 1.8,1.6
MCCT-D [mm]
  rect 2.6x2.4 smd: 1(-3.2,0) 2(3.2,0)
  silkscreen extent -4.2,-2.4 3.7,2.4
"SMD _LED" [mm]
  rect 1.3x1.6 smd: 1(0.95,0) 2(-0.95,0)
  silkscreen extent -2.13,-1.15 2,1.15
SO-G5/P.95 [mm]
  rect 0.55x1.45 smd: 1(-0.95,-1.075) 2(0,-1.075) 3(0.95,-1.075) 4(0.95,1.075) 5(-0.95,1.075)
  silkscreen extent -2.42,-2.2 1.65,2.2
SO-G44/P.8 [mm]
  rect 0.45x1.45 smd: 1(-8.4,-5.575) 2(-7.6,-5.575) 3(-6.8,-5.575) 4(-6,-5.575) 5(-5.2,-5.575) 6(-4.4,-5.575) 7(-3.6,-5.575) 8(-2.8,-5.575) 9(-2,-5.575) 10(-1.2,-5.575) 11(-0.4,-5.575) 12(0.4,-5.575) 13(1.2,-5.575) 14(2,-5.575) 15(2.8,-5.575) 16(3.6,-5.575) 17(4.4,-5.575) 18(5.2,-5.575) 19(6,-5.575) 20(6.8,-5.575) 21(7.6,-5.575) 22(8.4,-5.575) 23(8.4,5.575) 24(7.6,5.575) 25(6.8,5.575) 26(6,5.575) 27(5.2,5.575) 28(4.4,5.575) 29(3.6,5.575) 30(2.8,5.575) 31(2,5.575) 32(1.2,5.575) 33(0.4,5.575) 34(-0.4,5.575) 35(-1.2,5.575) 36(-2,5.575) 37(-2.8,5.575) 38(-3.6,5.575) 39(-4.4,5.575) 40(-5.2,5.575) 41(-6,5.575) 42(-6.8,5.575) 43(-7.6,5.575) 44(-8.4,5.575)
  silkscreen extent -9.3,-5.7 9.25,4.45
TestPin [mil] "SingleTest Pin"
  round 60 hole 35.43: 1(0,0)

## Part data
C1 C2 C3 C4 C5 C6 C50 C51: library part CAP_POLAR, "Polar Capacitor"
C7 C8 C9 C10 C11 C12 C13 C14 C15 C16 C17 C18 C19 C20 C21 C22 C23 C24 C25 C26 C27 C28 C29 C30 C31 C32 C33 C34 C35 C36 C37 C38 C39 C40 C41 C42 C43 C44 C45 C46 C47 C48 C49 C52 C53 C54 C55 C56 C57 C58 C59 C60 C61 C62 C63 C64 C65 C66 C67 C68 C69 C70 C71: library part CAP, "Capacitor"
HDR1 HDR2: "Board-to-Board, Docking Station, 0.80mm (.031\") Pitch, Shielded Receptacle, Vertical, Ultra Low Profile, SMT"
L1: library part Inductor, "Ferrite Bead"
LED1 LED2: library part HSMX-C670, "Typical RED GaAs SMD LED Agilent make"
R1 R2 R3 R5 R6 R7 R8 R9 R10 R11 R12: library part RES, "Resistor"
TP1 TP2 TP3 TP5 TP6 TP7 TP8 TP9 TP10 TP11 TP12 TP13 TP14: library part TestPin
TP4: library part TestPin, "QRNGEHJG"
U1: "Cyclone Family, 1.5V FPGA, 301 I/O Pins, 2 x PLLs, Commercial Grade, Speed Grade 8"
U2: library part SN74AHC1G04DBVR
U3 U4: "512Kx16Bit SRAM TSOP44"

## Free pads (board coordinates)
  round 1 smd mask+2: FID(4.2,20.6) FID(33.2,62.2) FID(61.4,21.8)
  round 1 smd far side mask+2: FID(5,23.8) FID(6.4,74.2) FID(58.6,75.2) FID(60.7,5.6)
  round 3.2 hole 3.5 unplated: LP(4,34) LP(65,4) LP(65,73)

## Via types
v1: diameter 0.6, hole 0.3, Top Layer to Bottom Layer, 453 vias

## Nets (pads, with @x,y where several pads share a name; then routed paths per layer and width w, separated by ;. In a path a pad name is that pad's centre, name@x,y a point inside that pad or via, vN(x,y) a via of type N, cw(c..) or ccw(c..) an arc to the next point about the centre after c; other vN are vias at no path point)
+5: HDR1.97 HDR1.99 HDR2.97 HDR2.99 | length 75.5
  Top Layer w0.2: v1(53.3,58.4) v1(54.1,58.4)
  Top Layer w1: v1(53.3,8.2) 55.4,8.2 56.8,9.6 56.8,23.6 53.6,26.8 53.6,43.2 61.7,51.3 61.7,57.6 60.6,58.7 54.4,58.7 v1(54.1,58.4) v1(54.1,57.5)
  Bottom Layer w0.3: v1(53.3,8.2) HDR2.97@53.3,9.7 ; v1(53.3,58.4) HDR1.97@53.3,60.5 ; v1(54.1,8.2) HDR2.99@54.1,9.7 ; v1(54.1,58.4) HDR1.99@54.1,60.5
  Bottom Layer w1: v1(53.3,58.4) v1(54.1,58.4) v1(54.1,57.5)
AUDIO_SPI_CSN: HDR1.11 U1.R17 | length 20.6
  MidLayer2 w0.127: 29.8,46.3 29.8,47.3
  MidLayer2 w0.2: v1(18.9,59) 26.5,51.4 27.3,51.4 29.8,48.9 29.8,47.3 ; v1(29.3,45.8) 29.8,46.3
  Bottom Layer w0.2: v1(18.9,59) HDR1.11@18.9,60.5 ; v1(29.3,45.8) U1.R17@29.8,45.3
BLUE0: HDR1.14 U1.U15 | length 37.8
  MidLayer2 w0.127: 25.8,44.3 26.8,44.3
  MidLayer2 w0.2: v1(19.7,68.8) 19.7,68.1 13,61.4 13,55.4 23.5,44.9 24.3,44.9 24.9,44.3 25.8,44.3 ; 26.8,44.3 v1(27.3,43.8)
  Bottom Layer w0.2: HDR1.14@19.7,67.3 v1(19.7,68.8) ; v1@27.5,43.6 v1(27.3,43.8) U1.U15@27.8,43.3
BLUE1: HDR1.16 U1.T16 | length 33.2
  MidLayer1 w0.127: 25.8,44.3 27.8,44.3
  MidLayer1 w0.2: v1(20.5,69.4) 20.5,64.8 23.3,62 23.3,46.2 25.2,44.3 25.8,44.3 ; 27.8,44.3 v1(28.3,43.8)
  Bottom Layer w0.2: HDR1.16@20.5,67.3 v1(20.5,69.4) ; v1(28.3,43.8) U1.T16@28.8,44.3
BOC_CTS: HDR1.13 U1.N18 | length 20.1
  MidLayer2 w0.2: v1(27.1,52.8) 27.6,52.8 27.9,52.5 31.3,49.1 v1(31.3,46.8)
  Bottom Layer w0.2: HDR1.13@19.7,60.6 HDR1.13@19.7,60.5 19.7,59.4 26.3,52.8 v1(27.1,52.8) ; v1(31.3,46.8) U1.N18@31.8,46.3
BOC_RTS: HDR1.17 U1.M16 | length 24.5
  MidLayer1 w0.127: 32.8,45.3 32.8,47.3
  MidLayer1 w0.2: v1(26.1,54.4) 26.1,54.9 26.9,55.7 27.5,55.7 32.8,50.4 32.8,47.3 ; v1(32.3,44.8) 32.8,45.3
  Bottom Layer w0.2: HDR1.17@21.3,60.7 21.3,59.5 22.2,58.6 26.1,54.7 v1(26.1,54.4) ; v1(32.3,44.8) U1.M16@32.8,44.3
BOC_RX: HDR1.19 U1.M18 | length 18.9
  MidLayer2 w0.2: v1@27.1,54.3 27.3,54.3 32.3,49.3 v1(32.3,46.8)
  Bottom Layer w0.2: HDR1.19@22.1,60.5 22.1,59.4 22.4,59.1 22.7,59.1 26.4,55.4 26.4,55 v1@27.1,54.3 ; v1(32.3,46.8) U1.M18@32.8,46.3
  other v1: 27.1,54.2
BOC_TX: HDR1.15 U1.N17 | length 21.4
  MidLayer2 w0.127: 31.8,46.3 31.8,47.3
  MidLayer2 w0.2: v1(26.5,53.5) 27.5,53.5 31.8,49.2 31.8,47.3 ; v1(31.3,45.8) 31.8,46.3
  Bottom Layer w0.2: HDR1.15@20.5,60.6 20.5,59.5 22,58 22,57.7 26.2,53.5 v1(26.5,53.5) ; v1@31.5,45.6 v1(31.3,45.8) U1.N17@31.8,45.3
BUZZER: HDR2.24 U1.V3 | length 16.1
  Bottom Layer w0.2: HDR2.24@23.7,16.5 23.7,17.6 26.2,20.1 26.2,28.9 26.3,29 26.3,30.8 U1.V3@26.8,31.3
CAN_RXD: HDR1.4 U1.T12 | length 39.9
  MidLayer1 w0.127: 25.8,40.3 27.8,40.3
  MidLayer1 w0.2: v1(15.7,69.4) 15.7,67.3 21.7,61.3 21.7,44 23.3,42.4 ; 22.92,42.78 25.4,40.3 25.8,40.3 ; 27.8,40.3 v1(28.3,39.8)
  Bottom Layer w0.2: HDR1.4@15.7,67.3 v1(15.7,69.4) ; v1@28.499,40 v1(28.3,39.8) U1.T12@28.8,40.3
CAN_TXD: HDR1.2 U1.T11 | length 38.9
  MidLayer1 w0.127: 25.9,39.3 27.8,39.3
  MidLayer1 w0.2: v1(14.9,68.8) 14.9,67.5 21.3,61.1 21.3,43.9 21.3,43.8 25.8,39.3 25.9,39.3 ; 27.8,39.3 v1(28.3,38.8)
  Bottom Layer w0.2: HDR1.2@14.9,67.3 v1(14.9,68.8) ; v1(28.3,38.8) U1.T11@28.8,39.3
FPGA_AUX0: HDR1.86 U1.C17 | length 36.6
  MidLayer1 w0.2: v1(42.3,44.8) 43.2,45.7 44.8,45.7 55,55.9 55,61.2 48.5,67.7 v1(48.5,69.4)
  Bottom Layer w0.2: U1.C17@41.8,45.3 v1(42.3,44.8) v1@42.101,44.999 ; HDR1.86@48.5,67.3 v1(48.5,69.4)
FPGA_AUX1: HDR1.88 U1.D16 | length 36.9
  MidLayer1 w0.127: v1(41.3,43.8) 41.8,44.3 42.8,44.3
  MidLayer1 w0.2: 42.8,44.3 43.8,45.3 45,45.3 55.4,55.7 55.4,61.4 49.3,67.5 v1(49.3,68.8)
  Bottom Layer w0.2: U1.D16@40.8,44.3 v1(41.3,43.8) ; HDR1.88@49.3,67.3 v1(49.3,68.8)
FPGA_AUX2: HDR1.90 U1.E15 | length 40.6
  MidLayer1 w0.127: 40.8,43.3 42.8,43.3
  MidLayer1 w0.2: v1(40.3,42.8) 40.8,43.3 ; 42.8,43.3 44.5,43.3 45.4,44.2 45.4,45.1 55.8,55.5 55.8,61.6 50.1,67.3 v1(50.1,69.4)
  Bottom Layer w0.2: U1.E15@39.8,43.3 v1(40.3,42.8) v1@40.101,42.999 ; HDR1.90@50.1,67.3 v1(50.1,69.4)
  other v1: 40.3,42.8 50.1,69.4
FPGA_AUX3: HDR1.92 U1.E14 | length 40.2
  MidLayer1 w0.127: 40.8,42.3 42.7,42.3
  MidLayer1 w0.2: v1(40.3,41.8) 40.8,42.3 ; 42.7,42.3 44.1,42.3 45.8,44 45.8,44.9 56.2,55.3 56.2,61.8 50.9,67.1 v1(50.9,68.8)
  Bottom Layer w0.2: U1.E14@39.8,42.3 v1(40.3,41.8) v1@40.101,41.999 ; HDR1.92@50.9,67.3 v1(50.9,68.8)
FPGA_CCLK: HDR1.66 R6.2 TP7.1 | length 65
  Top Layer w0.2: R6.2@40.25,22.9 41.15,23.8 47.7,23.8 50.2,26.3 50.8,26.9 50.8,49 40.9,58.9 40.9,64.2 40.5,64.6 v1(40.5,68.8)
  MidLayer1 w0.2: TP7.1@38,73 40.5,70.5 v1(40.5,68.8)
  Bottom Layer w0.2: HDR1.66@40.5,67.4 v1(40.5,68.8)
FPGA_CLK: HDR2.2 U1.K5 | length 37.2
  Top Layer w0.2: v1(14.9,18.2) 15.7,19 v1(34.6,19)
  MidLayer1 w0.2: v1(34.3,32.8) 34.3,30.4 33.2,29.3 33.2,22.9 34.6,21.5 v1(34.6,19)
  Bottom Layer w0.2: HDR2.2@14.9,16.6 v1(14.9,18.2) ; v1(34.3,32.8) U1.K5@34.8,33.3
FPGA_CLK_1: HDR1.30 U1.L14 | length 31.7
  MidLayer1 w0.127: 33.8,43.3 33.8,46.2
  MidLayer1 w0.2: v1(26.1,68.8) 26.1,60 26.1,57.9 33.3,50.7 33.3,46.9 33.8,46.4 33.8,46.2 ; 33.8,43.3 v1(34.3,42.8)
  Bottom Layer w0.2: HDR1.30@26.1,67.2 v1(26.1,68.8) ; U1.L14@33.8,42.3 v1(34.3,42.8)
FPGA_CLK_2: HDR1.32 U1.K14 | length 32.7
  MidLayer1 w0.127: 34.8,43.3 34.8,46.3
  MidLayer1 w0.2: v1(26.9,69.3) 26.9,59.8 26.9,57.7 33.7,50.9 33.7,47.4 33.9,47.2 34.8,46.3 ; 34.8,43.3 v1(35.3,42.8)
  Bottom Layer w0.2: HDR1.32@26.9,67.3 v1(26.9,69.3) ; U1.K14@34.8,42.3 v1(35.3,42.8)
FPGA_DIN: HDR1.64 TP8.1 U1.K3 | length 79.7
  Top Layer w0.2: v1(33.9,26.9) 34.5,26.3 36.1,26.3 38.2,24.2 47.5,24.2 50.2,26.9 50.4,27.1 50.4,48.8 40.5,58.7 40.5,64 40.1,64.4 39.9,64.6 39.9,69.5 v1(39.7,69.7)
  MidLayer1 w0.2: TP8.1@34.5,73 36.1,71.4 38,71.4 v1(39.7,69.7)
  Bottom Layer w0.2: v1(33.9,26.9) 33.9,27.7 34.4,28.2 34.4,28.7 34.3,28.8 34.3,30.8 U1.K3@34.8,31.3 ; HDR1.64@39.7,67.3 v1(39.7,69.7)
FPGA_DONE: HDR1.74 R1.2 U1.L18 U2.2 | length 109.2
  Top Layer w0.2: U2.2@25.6,4.6 25,4.6 24.6,5 24.6,6.3 24.2,6.7 15.7,6.7 15.3,6.3 14.7,6.3 14.3,6.7 14.3,19.1 15.8,20.6 15.8,32.7 20.8,37.7 20.8,50.1 29,58.3 v1(33.2,58.3) ; v1(43.7,69.3) R1.2@43.7,71
  MidLayer2 w0.2: v1(33.2,58.3) 35.8,58.3 43.7,66.2 v1(43.7,69.3)
  Bottom Layer w0.2: v1(33.2,58.3) 33.8,57.7 33.8,56.3 34.4,55.7 34.4,55.1 33.4,54.1 33.4,50.7 34.2,49.9 34.2,48.8 34.3,48.7 34.3,46.8 U1.L18@33.8,46.3 ; HDR1.74@43.7,67.3 v1(43.7,69.3)
  other v1: 43.7,69.3
FPGA_INIT: HDR1.68 R3.2 TP10.1 U1.L17 | length 51
  Top Layer w0.2: TP10.1@24,73 24.5,72.5 R3.2@24.5,71
  MidLayer2 w0.2: TP10.1@24,73 25.3,73 28.6,69.7 30.5,69.7 ; 33.3,47.5 33.3,49.5 29.4,53.4 29.4,66.8 30.5,67.9 30.5,69.7 ; v1(33.3,45.8) 33.3,47.5 ; v1(41.3,70.1) 40.6,70.8 31.6,70.8 30.5,69.7
  Bottom Layer w0.2: v1(33.3,45.8) U1.L17@33.8,45.3 ; HDR1.68@41.3,67.4 v1(41.3,70.1)
FPGA_M0: HDR1.60 U1.L1 | length 67.5
  Top Layer w0.2: v1(33.8,28.5) 35.4,28.5 38.5,25.4 46.9,25.4 49.2,27.7 49.2,48.2 39.3,58.1 39.3,63.4 38.1,64.6 v1(38.1,69.3) ; 47.6,26 48,26.4 ; 47.7,49.7 48,49.4
  Bottom Layer w0.2: v1@33.8,28.6 U1.L1@33.8,29.3 ; HDR1.60@38.1,67.3 v1(38.1,69.3)
FPGA_M1: HDR1.58 U1.L6 | length 78.7
  Top Layer w0.2: v1(34.8,26.9) 36,26.9 38.3,24.6 47.3,24.6 50,27.3 50,48.6 40.1,58.5 40.1,63.8 39.5,64.4 39.5,69.1 38.7,69.9 37.6,69.9 37.3,69.6 v1(37.3,68.8)
  MidLayer1 w0.127: 33.8,34.3 34.6,34.3 34.8,34.1 34.8,32.3
  MidLayer1 w0.2: v1(33.3,33.8) 33.8,34.3 ; v1(34.8,26.9) 34.2,27.5 34.2,28 34.4,28.2 34.4,28.7 34.3,28.8 34.3,29.4 34.625,29.725 34.625,32.125 34.8,32.3
  Bottom Layer w0.2: v1(33.3,33.8) U1.L6@33.8,34.3 ; HDR1.58@37.3,67.3 v1(37.3,68.8)
FPGA_M2: HDR1.56
FPGA_PROGRAM: HDR1.62 R2.2 TP9.1 U1.K1 | length 78.2
  Top Layer w0.2: TP9.1@31,73 32.1,71.9 R2.2@32.1,71.1 ; v1(34.8,27.8) 35.6,27.8 38.4,25 47.1,25 49.2,27.1 49.6,27.5 49.6,48.4 39.7,58.3 39.7,63.6 38.9,64.4 v1(38.9,68.8)
  MidLayer1 w0.2: TP9.1@31,73 33.1,70.9 37.7,70.9 38.9,69.7 v1(38.9,68.8)
  Bottom Layer w0.2: v1(34.8,27.8) U1.K1@34.8,29.3 ; HDR1.62@38.9,67.3 v1(38.9,68.8)
FPGA_TCK: HDR1.72 TP13.1 U1.L19 | length 35.2
  MidLayer2 w0.2: v1(33.2,57.3) 33,57.3 32.5,57.8 32.5,58.7 32.9,59.1 35.8,59.1 42.9,66.2 v1(42.9,68.8) 42.9,70.9 TP13.1@45,73
  Bottom Layer w0.2: v1(33.2,57.3) 32.6,56.7 32.6,50.3 33.3,49.6 33.3,47.8 U1.L19@33.8,47.3 ; HDR1.72@42.9,67.3 v1(42.9,68.8)
FPGA_TDI: HDR1.78 TP11.1 U1.K18 | length 36.4
  MidLayer2 w0.2: v1(34.4,57.3) 36.4,57.3 45.3,66.2 v1(45.3,69.3) 48.5,72.5 TP11.1@48.5,73
  Bottom Layer w0.2: v1(34.4,57.3) 34.4,56.4 35.1,55.7 35.1,49.8 35.4,49.5 35.4,48.8 35.3,48.7 35.3,46.8 U1.K18@34.8,46.3 ; HDR1.78@45.3,67.3 v1(45.3,69.3)
FPGA_TDO: HDR1.54 R7.1 TP12.1 | length 22.1
  Top Layer w0.2: v1(35.7,68.8) 35.7,63.8 36.1,63.4 R7.1@36.1,58.7
  MidLayer1 w0.2: TP12.1@27.5,73 30.1,70.4 34.9,70.4 35.7,69.6 v1(35.7,68.8)
  Bottom Layer w0.2: HDR1.54@35.7,67.4 v1(35.7,68.8)
FPGA_TMS: HDR1.70 TP14.1 U1.L16 | length 45.8
  MidLayer2 w0.127: 33.8,45.3 33.8,46.3
  MidLayer2 w0.2: v1(33.3,44.8) 33.8,45.3 ; 33.8,46.3 33.7,46.4 33.7,49.7 29.8,53.6 29.8,66.6 30.9,67.7 30.9,69.5 31.8,70.4 39.9,70.4 41,69.3 v1(42.1,69.3) 42.1,72.5 41.55,73.05 TP14.1@41.5,73.1
  Bottom Layer w0.2: v1(33.3,44.8) U1.L16@33.8,44.3 ; HDR1.70@42.1,67.3 v1(42.1,69.3)
GND: C1.2 C2.2 C3.2 C4.2 C5.2 C6.2 C7.2 C8.2 C9.2 C10.2 C11.2 C12.2 C13.2 C14.2 C15.2 C16.2 C17.1 C18.2 C19.2 C20.2 C21.2 C22.2 C23.2 C24.2 C25.2 C26.2 C27.2 C28.2 C29.2 C30.2 C31.2 C32.2 C33.2 C34.2 C35.2 C36.2 C37.2 C38.2 C39.2 C40.2 C41.2 C42.2 C43.2 C44.2 C45.2 C46.2 C47.2 C48.2 C49.2 C50.2 C51.2 C52.2 C53.2 C54.2 C55.2 C56.2 C57.2 C58.2 C59.2 C60.2 C61.2 C62.2 C63.2 C64.2 C65.2 C66.2 C67.2 C68.2 C69.2 C70.2 C71.2 HDR1.1 HDR1.36 HDR1.38 HDR1.40 HDR1.98 HDR1.100 HDR2.1 HDR2.98 HDR2.100 LED1.2 R9.2 U1.A1 U1.A3 U1.A18 U1.A20 U1.B2 U1.B19 U1.C1 U1.C20 U1.G8 U1.G9 U1.G10 U1.G11 U1.G12 U1.G13 U1.H9 U1.H11 U1.J10 U1.J12 U1.K7 U1.K9 U1.K11 U1.K20 U1.L5 U1.L7 U1.L10 U1.L12 U1.L15 U1.M9 U1.M11 U1.N10 U1.N12 U1.P8 U1.P9 U1.P10 U1.P11 U1.P12 U1.P13 U1.V1 U1.V20 U1.W2 U1.W19 U1.Y1 U1.Y3 U1.Y18 U1.Y20 U2.3 U3.12 U3.34 U4.12 U4.34 | length 199
  Top Layer w0.2: C9.2@21.7,32.1 23.4,32.1 v1(24,31.5) ; C32.2@21.7,45.4 23,45.4 23.2,45.4 v1(24.1,46.3) ; C63.2@21.8,28.7 23,28.7 23.4,28.7 24.5,29.8 v1(25.3,29.8) ; C58.2@21.8,48.9 23.5,48.9 24.3,48.1 25,48.1 v1(25.3,47.8) ; C34.2@23,32.1 C34.2@23.025,32.075 ; C57.2@24.3,26.2 v1@24.3,28.8 ; v1(24.3,48.8) C59.2@24.3,51.5 ; U2.3@25.65,5.5 27.5,5.5 C17.1@27.9,5.1 ; v1(26.8,28.5) 27.8,27.5 C41.2@27.9,27.5 ; v1@27,49.2 v1(26.8,49) 27.7,49.9 27.7,51.4 C15.2@27.8,51.5 ; C21.2@29.1,39.8 29.3,39.8 v1(30.3,38.8) v1@30.2,38.7 ; C38.2@29.3,43 29.7,43 30,42.7 30.3,42.7 v1(30.3,41.8) ; C30.2@29.9,34.6 30.3,35 C49.2@30.9,35 ; C27.2@30.2,38 31,38.8 v1(31.3,38.8) ; C31.2@30.3,42.6 30.9,42.6 31.2,42.6 31.3,42.7 C8.2@31.3,43.2 ; C13.2@30.9,34.1 30.9,35.4 v1(31.3,35.8) v1(31.3,36.8) v1(32.3,37.8) ; v1(33.3,40.8) 34.3,41.8 C24.2@34.4,41.8 ; v1(33.3,42.8) C54.2@34.2,43.7 ; v1@34.2,39.9 34.4,39.7 C20.2@35.3,39.7 ; v1(34.3,34.8) 34.4,34.9 C55.2@35.3,34.9 ; v1(34.3,37.8) 34.3,37 34.5,36.8 C23.2@34.5,35.9 ; v1(35.3,38.8) 34.9,38.4 34.9,37.6 35.5,37 C26.2@35.5,36.6 ; C22.2@36.3,34.7 37.3,35.7 v1(37.3,35.8) 38.1,35.8 38.1,35.6 C47.2@39,35.6 ; v1(36.3,39.8) C36.2@36.3,40.7 ; v1(36.3,42.8) 37,42.8 C25.2@37.1,42.9 ; v1(36.3,43.8) C19.2@37.1,43.8 ; v1(37.3,40.8) 38.3,41.8 C18.2@38.3,41.9 ; v1(38.3,38.8) 38.7,38.4 C44.2@39.3,38.4 ; C16.2@40.8,26.2 40.825,26.225 40.9,26.3 40.9,27.7 v1@41.7,28.5 ; C14.2@40.9,51.3 40.9,50 41.8,49.1 v1(41.8,49) ; v1@41.7,28.4 v1(41.8,28.5) ; v1(43.3,29.8) 43.4,29.7 43.4,28.84 44.3,27.94 C65.2@44.3,27.4 ; v1(43.3,47.8) 44.3,48.8 C56.2@44.3,51.2 ; C62.2@44.3,26.2 C65.2@44.3,27.5 ; v1(44.3,28.8) 44.4,28.7 C61.2@47.1,28.7 ; v1@44.5,31.3 45.3,32.1 45.7,32.1 C43.2@47,32.1 ; v1(44.6,46.3) 45.5,45.4 45.7,45.4 C11.2@47.1,45.4 ; v1@44.6,48.3 45,48.7 C60.2@47,48.7 ; C29.2@46.3,3 v1(47.5,3) ; C29.2@46.35,3 46.35,4.05 46.5,4.2 50.1,4.2 50.4,4.5 LED1.2@50.4,5.5
  Top Layer w0.3: v1(5.2,47.9) 5.7,48.4 7.4,48.4 8,49 C4.2@9.5,49 9,48.5 v1(9,47.5) ; C12.2@12.2,46.7 v1(13.4,46.7) ; C1.2@18.9,28.8 19,28.7 C63.2@21.7,28.7 ; U2.3@25.6,5.5 v1(25.6,6.7) ; C41.2@27.95,27.5 27.95,24.95 28.8,24.1 v1(28.8,23.5) ; C2.2@32.9,53.5 33.4,54 v1@34.3,54 ; v1(34.4,22.6) 35.5,22.6 C3.2@35.9,23 ; v1(34.8,49) 35.2,49.4 C52.2@35.2,50.1 ; R9.2@47,62.9 47,64.2 47.6,64.8 51.6,64.8 54.1,67.3 v1(54.1,68.8) ; v1(53.4,50.8) C6.2@55,50.8 ; v1(55.7,41.5) 55.9,41.7 C39.2@57.1,41.7 ; v1(57.3,72) C51.2@59.1,72 ; v1(59.1,70.3) C51.2@59.1,72.1 ; C5.2@60,39.3 60.6,39.9 C40.2@62.7,39.9 ; C5.2@60,39.5 61,38.5 v1(61.7,38.5) ; v1(60.2,56) 58.9,56 C50.2@58.3,56.6 59,57.3 v1(60.2,57.3) ; v1(62.5,38.8) 63,39.3 C40.2@63,40.2 ; C40.2@63,40.1 64,40.1 v1(64.2,40.3)
  Bottom Layer w0.2: U4.12@3.925,47.9 v1(5.2,47.9) ; v1(13.4,46.7) 13.8,47.1 U4.34@15.075,47.1 ; HDR1.1@14.7,60.5 HDR1.1@14.9,60.5 v1(14.9,58.5) v1(14.9,57.7) ; v1(14.9,8.2) HDR2.1@14.9,9.7 ; v1(24,31.5) 24.6,31.5 U1.Y3@24.8,31.3 ; v1(24.1,46.3) U1.Y18@24.8,46.3 ; v1(24.3,28.8) U1.Y1@24.8,29.3 ; v1(24.3,48.8) U1.Y20@24.8,48.3 ; v1(25.3,47.8) U1.W19@25.8,47.3 ; v1(25.3,29.8) U1.W2@25.8,30.3 ; v1@26.8,28.6 U1.V1@26.8,29.3 ; U1.V20@26.8,48.3 v1(26.8,49) ; HDR1.36@28.5,67.2 28.5,68.8 30.1,68.8 HDR1.40@30.1,67.3 ; HDR1.38@29.3,67.3 v1(29.3,68.8) ; v1(30.3,40.8) U1.P12@30.8,40.3 ; v1(30.3,41.8) U1.P13@30.8,41.3 ; U1.P8@30.8,36.3 v1(31.3,35.8) ; U1.P9@30.8,37.3 v1(31.3,36.8) ; U1.P10@30.8,38.3 v1(30.3,38.8) U1.P11@30.8,39.3 ; v1(31.3,38.8) U1.N10@31.8,38.3 ; v1(31.3,40.8) U1.N12@31.8,40.3 ; v1(32.3,37.8) U1.M9@32.8,37.3 ; v1(32.3,39.8) U1.M11@32.8,39.3 ; v1(33.3,34.8) U1.L7@33.8,35.3 v1(34.3,34.8) ; v1(33.3,32.8) U1.L5@33.8,33.3 ; v1(33.3,38.8) U1.L10@33.8,38.3 ; v1(33.3,40.8) U1.L12@33.8,40.3 ; v1(33.3,42.8) U1.L15@33.8,43.3 ; v1(34.3,34.8) U1.K7@34.8,35.3 ; v1(34.3,37.8) U1.K9@34.8,37.3 ; v1(34.3,39.8) U1.K11@34.8,39.3 ; U1.K20@34.8,48.3 v1(34.8,49) ; v1(35.3,38.8) U1.J10@35.8,38.3 ; U1.J12@35.8,40.3 v1(36.3,39.8) ; v1(36.3,39.8) U1.H11@36.8,39.3 ; U1.H9@36.8,37.3 v1(37.3,37.8) U1.G9@37.8,37.3 ; v1(37.3,35.8) U1.G8@37.8,36.3 ; v1(37.3,38.8) U1.G10@37.8,38.3 ; U1.G11@37.8,39.3 v1(38.3,38.8) ; U1.G12@37.8,40.3 v1(37.3,40.8) U1.G13@37.8,41.3 ; v1@41.8,28.6 U1.C1@41.8,29.3 ; U1.C20@41.8,48.3 v1(41.8,49) ; U1.B2@42.8,30.3 v1(43.3,29.8) ; U1.B19@42.8,47.3 v1(43.3,47.8) ; U1.A1@43.8,29.3 v1(44.3,28.8) ; U1.A3@43.8,31.3 v1@44.5,31.3 ; U1.A18@43.8,46.3 v1(44.6,46.3) ; U1.A20@43.8,48.3 v1@44.6,48.3
  Bottom Layer w0.3: v1(14.9,7.1) v1(14.9,8.2) ; HDR2.98@53.3,16.5 v1(53.3,18.6) ; HDR1.98@53.3,67.3 v1(53.3,69) v1(53.9,69.6) ; HDR1.100@54,67.3 HDR1.100@54.1,67.4 ; HDR2.100@54.1,16.5 v1(54.1,18.6) ; HDR1.100@54.1,67.3 v1(54.1,68.8) v1(54.9,69.6) ; U3.12@54.3,41.4 55.6,41.4 v1(55.7,41.5) ; v1(64.2,40.3) 64.5,40.6 U3.34@65.5,40.6
  other v1: 44.6,31.3 44.6,48.4 34.4,54
GREEN0: HDR1.10 U1.T15 | length 34.8
  MidLayer1 w0.127: 24.8,43.3 27.8,43.3
  MidLayer1 w0.2: v1(18.1,68.8) 18.1,66.7 22.9,61.9 22.9,44.6 24.2,43.3 24.8,43.3 ; 27.8,43.3 v1(28.3,42.8)
  Bottom Layer w0.2: HDR1.10@18.1,67.3 v1(18.1,68.8) ; v1@28.499,42.999 v1(28.3,42.8) U1.T15@28.8,43.3
GREEN1: HDR1.12 U1.V16 | length 38.4
  MidLayer2 w0.2: 12.6,61.8 12.6,61.9 ; v1(18.9,69.5) 18.9,68.2 12.6,61.9 ; v1(26.3,43.8) 24.4,43.8 24.3,43.7 23.9,43.7 12.6,55 12.6,61.9
  Bottom Layer w0.2: HDR1.12@18.9,67.4 v1(18.9,69.5) ; v1(26.3,43.8) U1.V16@26.8,44.3
HDRIVE: HDR1.18 U1.V17 | length 36.1
  MidLayer2 w0.2: v1(21.3,68.8) 13.4,60.9 13.4,55.6 23.7,45.3 24.5,45.3 25,44.8 v1(26.3,44.8)
  Bottom Layer w0.2: HDR1.18@21.3,67.3 v1(21.3,68.8) ; v1(26.3,44.8) U1.V17@26.8,45.3
IO0: HDR2.7 U1.U6 | length 35.5
  MidLayer2 w0.127: 25.8,34.3 26.8,34.3
  MidLayer2 w0.2: v1(17.3,7.6) 17.3,8.3 22.3,13.3 22.3,31.7 22.9,32.3 23.1,32.5 24.4,32.5 25.779,33.879 25.779,34.279 25.8,34.3 ; 26.8,34.3 v1(27.3,34.8)
  Bottom Layer w0.2: v1(17.3,7.6) HDR2.7@17.3,9.7 ; v1(27.3,34.8) U1.U6@27.8,34.3
IO1: HDR2.9 U1.V5 | length 32.2
  MidLayer2 w0.2: v1(18.1,8.2) 22.7,12.8 22.7,31.5 23.3,32.1 24.6,32.1 v1(26.3,33.8)
  Bottom Layer w0.2: v1(18.1,8.2) HDR2.9@18.1,9.7 ; v1@26.5,33.6 v1(26.3,33.8) U1.V5@26.8,33.3
IO2: HDR2.11 U1.U5 | length 33.2
  MidLayer2 w0.2: v1(18.9,7.6) 18.9,8.4 23.1,12.6 23.1,30.6 23.4,30.9 25.4,30.9 25.8,31.3 25.8,32.3 v1(26.3,32.8)
  Bottom Layer w0.2: v1(18.9,7.6) HDR2.11@18.9,9.7 ; v1(26.3,32.8) 27.3,32.8 U1.U5@27.8,33.3
IO3: HDR2.13 U1.R6 | length 32.7
  MidLayer2 w0.2: v1(19.7,8.2) 24,12.5 24,18.5 25,19.5 25,28.7 26.3,30 26.3,31.8 28.3,33.8 v1(29.3,33.8)
  Bottom Layer w0.2: v1(19.7,8.2) HDR2.13@19.7,9.7 ; v1@29.499,34 v1(29.3,33.8) U1.R6@29.8,34.3
IO4: HDR2.15 U1.T5 | length 32.1
  MidLayer1 w0.127: 28.8,30.3 28.8,32.3
  MidLayer1 w0.2: v1(20.5,7.6) 20.5,8.3 29.4,17.2 29.4,29.7 28.8,30.3 ; v1(28.3,32.8) 28.8,32.3
  Bottom Layer w0.2: v1(20.5,7.6) HDR2.15@20.5,9.7 ; v1(28.3,32.8) U1.T5@28.8,33.3
IO5: HDR2.17 U1.R5 | length 30.5
  MidLayer1 w0.127: 29.8,30.3 29.8,32.3
  MidLayer1 w0.2: v1(21.3,8.2) 29.8,16.7 29.8,30.3 ; v1(29.3,32.8) 29.8,32.3
  Bottom Layer w0.2: v1(21.3,8.2) HDR2.17@21.3,9.7 ; v1(29.3,32.8) U1.R5@29.8,33.3
IO6: HDR2.19 U1.P5 | length 32.1
  MidLayer1 w0.127: 30.8,30.3 30.8,32.3
  MidLayer1 w0.2: v1(22.1,7.6) 22.1,8.3 30.8,17 30.8,30.3 ; v1(30.3,32.8) 30.8,32.3
  Bottom Layer w0.2: v1(22.1,7.6) HDR2.19@22.1,9.7 ; v1@30.499,33 v1(30.3,32.8) U1.P5@30.8,33.3
IO7: HDR2.21 U1.N5 | length 31
  MidLayer1 w0.127: 31.8,30.3 31.8,32.3
  MidLayer1 w0.2: v1(22.9,8.2) 31.8,17.1 31.8,30.3 ; v1(31.3,32.8) 31.8,32.3
  Bottom Layer w0.2: v1(22.9,8.2) HDR2.21@22.9,9.7 ; v1@31.5,32.999 v1(31.3,32.8) U1.N5@31.8,33.3
IO8: HDR2.23 U1.M5 | length 32
  MidLayer1 w0.127: 32.8,30.3 32.8,32.3
  MidLayer1 w0.2: v1(23.7,7.6) 23.7,8.4 32.4,17.1 32.4,29.9 32.8,30.3 ; v1(32.3,32.8) 32.8,32.3
  Bottom Layer w0.2: v1(23.7,7.6) HDR2.23@23.7,9.7 ; v1(32.3,32.8) U1.M5@32.8,33.3
IO9: HDR2.25 U1.V4 | length 27
  MidLayer2 w0.2: v1(24.5,8.2) 24.5,18.2 26.2,19.9 26.2,28.9 27,29.7 27,30.3 27.3,30.6 v1(27.3,31.8)
  Bottom Layer w0.2: v1(24.5,8.2) HDR2.25@24.5,9.7 ; U1.V4@26.8,32.3 v1(27.3,31.8)
IO10: HDR2.27 U1.U4 | length 28.5
  MidLayer2 w0.127: 27.8,30.3 27.8,31.3 v1(28.3,31.8)
  MidLayer2 w0.2: v1(25.3,7.6) 25.3,18.4 27.4,20.5 27.4,29.9 27.8,30.3
  Bottom Layer w0.2: v1(25.3,7.6) HDR2.27@25.3,9.7 ; U1.U4@27.8,32.3 v1(28.3,31.8) v1@28.101,31.999
IO11: HDR2.29 U1.U3 | length 25.7
  MidLayer2 w0.2: v1(26.1,8.2) 26.1,18.4 27.8,20.1 27.8,29.3 28.3,29.8 v1(28.3,30.8)
  Bottom Layer w0.2: v1(26.1,8.2) HDR2.29@26.1,9.7 ; U1.U3@27.8,31.3 v1(28.3,30.8)
IO12: HDR2.31 U1.T4 | length 28.3
  MidLayer2 w0.127: 28.8,30.3 28.8,31.3 v1(29.3,31.8)
  MidLayer2 w0.2: v1(26.9,7.6) 26.9,18.4 28.2,19.7 28.2,28.8 28.8,29.4 28.8,30.3
  Bottom Layer w0.2: v1(26.9,7.6) HDR2.31@26.9,9.7 ; U1.T4@28.8,32.3 v1(29.3,31.8) v1@29.101,31.999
